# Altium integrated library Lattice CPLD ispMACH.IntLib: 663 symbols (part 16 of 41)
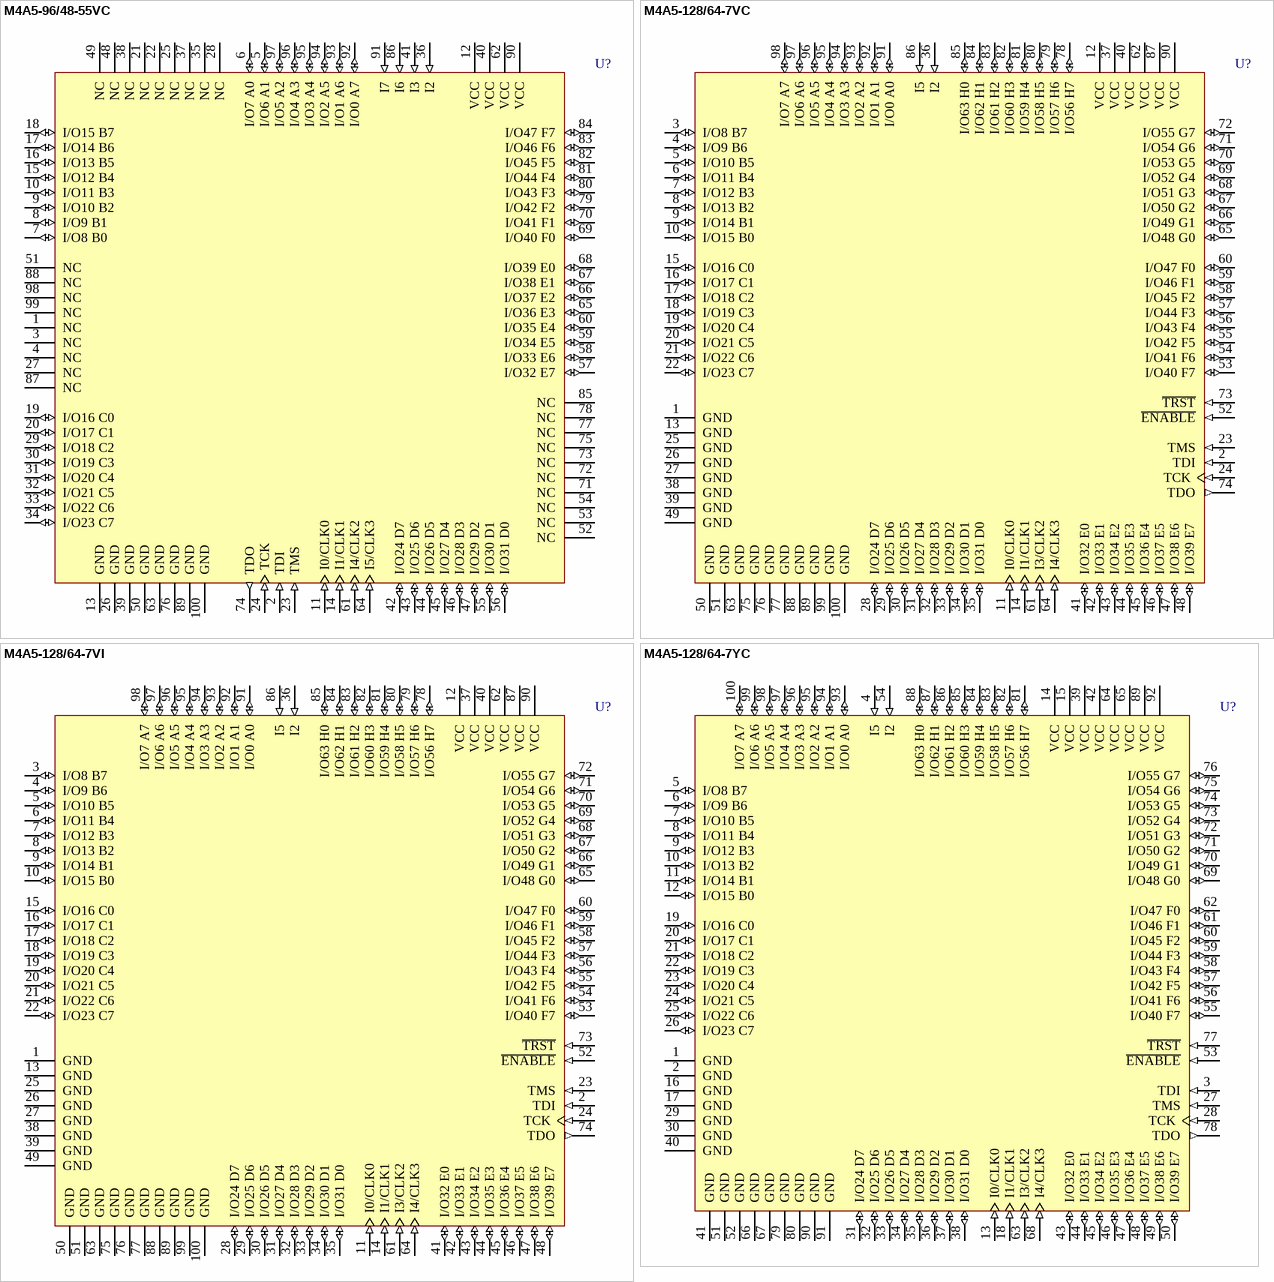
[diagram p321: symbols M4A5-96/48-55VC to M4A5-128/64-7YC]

## M4A5-128/64-7VC
designator U?
High-Performance EE CMOS In-System Programmable Logic
footprint TQFP100_N (Thin QFP, 100-Leads, Body 14x14mm, Pitch 0.5mm, IPC Medium Density)
footprint TQFP100_L (Thin QFP, 100-Leads, Body 14x14mm, Pitch 0.5mm, IPC High Density)
footprint TQFP100_M (Thin QFP, 100-Leads, Body 14x14mm, Pitch 0.5mm, IPC Low Density)
3D model M4A5-TQFP100 (100-Pin Thin Quad Flat Pack (TQFP100))
pins: 1 GND (power), 2 TDI (in), 3 I/O8 B7 (io), 4 I/O9 B6 (io), 5 I/O10 B5 (io), 6 I/O11 B4 (io), 7 I/O12 B3 (io), 8 I/O13 B2 (io), 9 I/O14 B1 (io), 10 I/O15 B0 (io), 11 I0/CLK0 (in), 12 VCC (power), 13 GND (power), 14 I1/CLK1 (in), 15 I/O16 C0 (io), 16 I/O17 C1 (io), 17 I/O18 C2 (io), 18 I/O19 C3 (io), 19 I/O20 C4 (io), 20 I/O21 C5 (io), 21 I/O22 C6 (io), 22 I/O23 C7 (io), 23 TMS (in), 24 TCK (in), 25 GND (power), 26 GND (power), 27 GND (power), 28 I/O24 D7 (io), 29 I/O25 D6 (io), 30 I/O26 D5 (io), 31 I/O27 D4 (io), 32 I/O28 D3 (io), 33 I/O29 D2 (io), 34 I/O30 D1 (io), 35 I/O31 D0 (io), 36 I2 (in), 37 VCC (power), 38 GND (power), 39 GND (power), 40 VCC (power), 41 I/O32 E0 (io), 42 I/O33 E1 (io), 43 I/O34 E2 (io), 44 I/O35 E3 (io), 45 I/O36 E4 (io), 46 I/O37 E5 (io), 47 I/O38 E6 (io), 48 I/O39 E7 (io), 49 GND (power), 50 GND (power), 51 GND (power), 52 ~{ENABLE} (in), 53 I/O40 F7 (io), 54 I/O41 F6 (io), 55 I/O42 F5 (io), 56 I/O43 F4 (io), 57 I/O44 F3 (io), 58 I/O45 F2 (io), 59 I/O46 F1 (io), 60 I/O47 F0 (io), 61 I3/CLK2 (in), 62 VCC (power), 63 GND (power), 64 I4/CLK3 (in), 65 I/O48 G0 (io), 66 I/O49 G1 (io), 67 I/O50 G2 (io), 68 I/O51 G3 (io), 69 I/O52 G4 (io), 70 I/O53 G5 (io), 71 I/O54 G6 (io), 72 I/O55 G7 (io), 73 ~{TRST} (in), 74 TDO (out), 75 GND (power), 76 GND (power), 77 GND (power), 78 I/O56 H7 (io), 79 I/O57 H6 (io), 80 I/O58 H5 (io), 81 I/O59 H4 (io), 82 I/O60 H3 (io), 83 I/O61 H2 (io), 84 I/O62 H1 (io), 85 I/O63 H0 (io), 86 I5 (in), 87 VCC (power), 88 GND (power), 89 GND (power), 90 VCC (power), 91 I/O0 A0 (io), 92 I/O1 A1 (io), 93 I/O2 A2 (io), 94 I/O3 A3 (io), 95 I/O4 A4 (io), 96 I/O5 A5 (io), 97 I/O6 A6 (io), 98 I/O7 A7 (io), 99 GND (power), 100 GND (power)

## M4A5-128/64-7VI
designator U?
High-Performance EE CMOS In-System Programmable Logic
footprint TQFP100_N (Thin QFP, 100-Leads, Body 14x14mm, Pitch 0.5mm, IPC Medium Density)
footprint TQFP100_L (Thin QFP, 100-Leads, Body 14x14mm, Pitch 0.5mm, IPC High Density)
footprint TQFP100_M (Thin QFP, 100-Leads, Body 14x14mm, Pitch 0.5mm, IPC Low Density)
3D model M4A5-TQFP100 (100-Pin Thin Quad Flat Pack (TQFP100))
pins: 1 GND (power), 2 TDI (in), 3 I/O8 B7 (io), 4 I/O9 B6 (io), 5 I/O10 B5 (io), 6 I/O11 B4 (io), 7 I/O12 B3 (io), 8 I/O13 B2 (io), 9 I/O14 B1 (io), 10 I/O15 B0 (io), 11 I0/CLK0 (in), 12 VCC (power), 13 GND (power), 14 I1/CLK1 (in), 15 I/O16 C0 (io), 16 I/O17 C1 (io), 17 I/O18 C2 (io), 18 I/O19 C3 (io), 19 I/O20 C4 (io), 20 I/O21 C5 (io), 21 I/O22 C6 (io), 22 I/O23 C7 (io), 23 TMS (in), 24 TCK (in), 25 GND (power), 26 GND (power), 27 GND (power), 28 I/O24 D7 (io), 29 I/O25 D6 (io), 30 I/O26 D5 (io), 31 I/O27 D4 (io), 32 I/O28 D3 (io), 33 I/O29 D2 (io), 34 I/O30 D1 (io), 35 I/O31 D0 (io), 36 I2 (in), 37 VCC (power), 38 GND (power), 39 GND (power), 40 VCC (power), 41 I/O32 E0 (io), 42 I/O33 E1 (io), 43 I/O34 E2 (io), 44 I/O35 E3 (io), 45 I/O36 E4 (io), 46 I/O37 E5 (io), 47 I/O38 E6 (io), 48 I/O39 E7 (io), 49 GND (power), 50 GND (power), 51 GND (power), 52 ~{ENABLE} (in), 53 I/O40 F7 (io), 54 I/O41 F6 (io), 55 I/O42 F5 (io), 56 I/O43 F4 (io), 57 I/O44 F3 (io), 58 I/O45 F2 (io), 59 I/O46 F1 (io), 60 I/O47 F0 (io), 61 I3/CLK2 (in), 62 VCC (power), 63 GND (power), 64 I4/CLK3 (in), 65 I/O48 G0 (io), 66 I/O49 G1 (io), 67 I/O50 G2 (io), 68 I/O51 G3 (io), 69 I/O52 G4 (io), 70 I/O53 G5 (io), 71 I/O54 G6 (io), 72 I/O55 G7 (io), 73 ~{TRST} (in), 74 TDO (out), 75 GND (power), 76 GND (power), 77 GND (power), 78 I/O56 H7 (io), 79 I/O57 H6 (io), 80 I/O58 H5 (io), 81 I/O59 H4 (io), 82 I/O60 H3 (io), 83 I/O61 H2 (io), 84 I/O62 H1 (io), 85 I/O63 H0 (io), 86 I5 (in), 87 VCC (power), 88 GND (power), 89 GND (power), 90 VCC (power), 91 I/O0 A0 (io), 92 I/O1 A1 (io), 93 I/O2 A2 (io), 94 I/O3 A3 (io), 95 I/O4 A4 (io), 96 I/O5 A5 (io), 97 I/O6 A6 (io), 98 I/O7 A7 (io), 99 GND (power), 100 GND (power)

## M4A5-128/64-7YC
designator U?
High-Performance EE CMOS In-System Programmable Logic
footprint PQFP100_N (QFP, 100-Leads, Body 20x14mm, Pitch 0.65mm, IPC Medium Density)
footprint PQFP100_L (QFP, 100-Leads, Body 20x14mm, Pitch 0.65mm, IPC High Density)
footprint PQFP100_M (QFP, 100-Leads, Body 20x14mm, Pitch 0.65mm, IPC Low Density)
3D model PQFP-100 (100-Pin Quad Flat Pack Rectangular 0.65 mm Pitch)
pins: 1 GND (power), 2 GND (power), 3 TDI (in), 4 I5 (in), 5 I/O8 B7 (io), 6 I/O9 B6 (io), 7 I/O10 B5 (io), 8 I/O11 B4 (io), 9 I/O12 B3 (io), 10 I/O13 B2 (io), 11 I/O14 B1 (io), 12 I/O15 B0 (io), 13 I0/CLK0 (in), 14 VCC (power), 15 VCC (power), 16 GND (power), 17 GND (power), 18 I1/CLK1 (in), 19 I/O16 C0 (io), 20 I/O17 C1 (io), 21 I/O18 C2 (io), 22 I/O19 C3 (io), 23 I/O20 C4 (io), 24 I/O21 C5 (io), 25 I/O22 C6 (io), 26 I/O23 C7 (io), 27 TMS (in), 28 TCK (in), 29 GND (power), 30 GND (power), 31 I/O24 D7 (io), 32 I/O25 D6 (io), 33 I/O26 D5 (io), 34 I/O27 D4 (io), 35 I/O28 D3 (io), 36 I/O29 D2 (io), 37 I/O30 D1 (io), 38 I/O31 D0 (io), 39 VCC (power), 40 GND (power), 41 GND (power), 42 VCC (power), 43 I/O32 E0 (io), 44 I/O33 E1 (io), 45 I/O34 E2 (io), 46 I/O35 E3 (io), 47 I/O36 E4 (io), 48 I/O37 E5 (io), 49 I/O38 E6 (io), 50 I/O39 E7 (io), 51 GND (power), 52 GND (power), 53 ~{ENABLE} (in), 54 I2 (in), 55 I/O40 F7 (io), 56 I/O41 F6 (io), 57 I/O42 F5 (io), 58 I/O43 F4 (io), 59 I/O44 F3 (io), 60 I/O45 F2 (io), 61 I/O46 F1 (io), 62 I/O47 F0 (io), 63 I3/CLK2 (in), 64 VCC (power), 65 VCC (power), 66 GND (power), 67 GND (power), 68 I4/CLK3 (in), 69 I/O48 G0 (io), 70 I/O49 G1 (io), 71 I/O50 G2 (io), 72 I/O51 G3 (io), 73 I/O52 G4 (io), 74 I/O53 G5 (io), 75 I/O54 G6 (io), 76 I/O55 G7 (io), 77 ~{TRST} (in), 78 TDO (out), 79 GND (power), 80 GND (power), 81 I/O56 H7 (io), 82 I/O57 H6 (io), 83 I/O58 H5 (io), 84 I/O59 H4 (io), 85 I/O60 H3 (io), 86 I/O61 H2 (io), 87 I/O62 H1 (io), 88 I/O63 H0 (io), 89 VCC (power), 90 GND (power), 91 GND (power), 92 VCC (power), 93 I/O0 A0 (io), 94 I/O1 A1 (io), 95 I/O2 A2 (io), 96 I/O3 A3 (io), 97 I/O4 A4 (io), 98 I/O5 A5 (io), 99 I/O6 A6 (io), 100 I/O7 A7 (io)

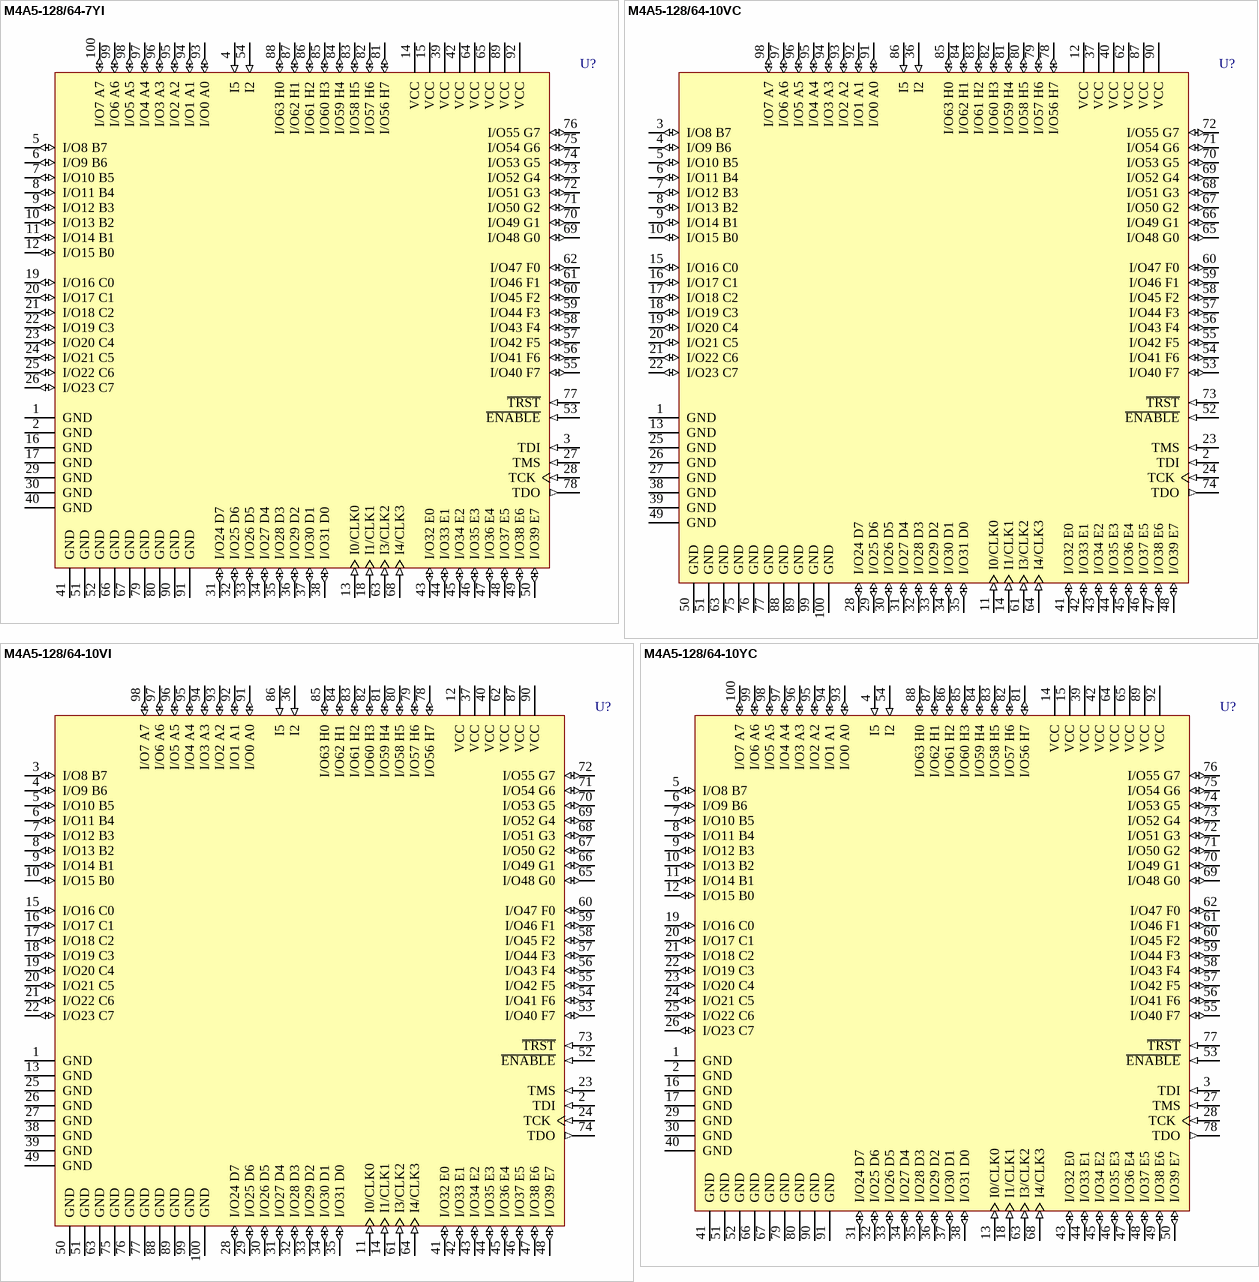
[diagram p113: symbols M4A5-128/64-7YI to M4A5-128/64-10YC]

## M4A5-128/64-7YI
designator U?
High-Performance EE CMOS In-System Programmable Logic
footprint PQFP100_N (QFP, 100-Leads, Body 20x14mm, Pitch 0.65mm, IPC Medium Density)
footprint PQFP100_L (QFP, 100-Leads, Body 20x14mm, Pitch 0.65mm, IPC High Density)
footprint PQFP100_M (QFP, 100-Leads, Body 20x14mm, Pitch 0.65mm, IPC Low Density)
3D model PQFP-100 (100-Pin Quad Flat Pack Rectangular 0.65 mm Pitch)
pins: 1 GND (power), 2 GND (power), 3 TDI (in), 4 I5 (in), 5 I/O8 B7 (io), 6 I/O9 B6 (io), 7 I/O10 B5 (io), 8 I/O11 B4 (io), 9 I/O12 B3 (io), 10 I/O13 B2 (io), 11 I/O14 B1 (io), 12 I/O15 B0 (io), 13 I0/CLK0 (in), 14 VCC (power), 15 VCC (power), 16 GND (power), 17 GND (power), 18 I1/CLK1 (in), 19 I/O16 C0 (io), 20 I/O17 C1 (io), 21 I/O18 C2 (io), 22 I/O19 C3 (io), 23 I/O20 C4 (io), 24 I/O21 C5 (io), 25 I/O22 C6 (io), 26 I/O23 C7 (io), 27 TMS (in), 28 TCK (in), 29 GND (power), 30 GND (power), 31 I/O24 D7 (io), 32 I/O25 D6 (io), 33 I/O26 D5 (io), 34 I/O27 D4 (io), 35 I/O28 D3 (io), 36 I/O29 D2 (io), 37 I/O30 D1 (io), 38 I/O31 D0 (io), 39 VCC (power), 40 GND (power), 41 GND (power), 42 VCC (power), 43 I/O32 E0 (io), 44 I/O33 E1 (io), 45 I/O34 E2 (io), 46 I/O35 E3 (io), 47 I/O36 E4 (io), 48 I/O37 E5 (io), 49 I/O38 E6 (io), 50 I/O39 E7 (io), 51 GND (power), 52 GND (power), 53 ~{ENABLE} (in), 54 I2 (in), 55 I/O40 F7 (io), 56 I/O41 F6 (io), 57 I/O42 F5 (io), 58 I/O43 F4 (io), 59 I/O44 F3 (io), 60 I/O45 F2 (io), 61 I/O46 F1 (io), 62 I/O47 F0 (io), 63 I3/CLK2 (in), 64 VCC (power), 65 VCC (power), 66 GND (power), 67 GND (power), 68 I4/CLK3 (in), 69 I/O48 G0 (io), 70 I/O49 G1 (io), 71 I/O50 G2 (io), 72 I/O51 G3 (io), 73 I/O52 G4 (io), 74 I/O53 G5 (io), 75 I/O54 G6 (io), 76 I/O55 G7 (io), 77 ~{TRST} (in), 78 TDO (out), 79 GND (power), 80 GND (power), 81 I/O56 H7 (io), 82 I/O57 H6 (io), 83 I/O58 H5 (io), 84 I/O59 H4 (io), 85 I/O60 H3 (io), 86 I/O61 H2 (io), 87 I/O62 H1 (io), 88 I/O63 H0 (io), 89 VCC (power), 90 GND (power), 91 GND (power), 92 VCC (power), 93 I/O0 A0 (io), 94 I/O1 A1 (io), 95 I/O2 A2 (io), 96 I/O3 A3 (io), 97 I/O4 A4 (io), 98 I/O5 A5 (io), 99 I/O6 A6 (io), 100 I/O7 A7 (io)

## M4A5-128/64-10VC
designator U?
High-Performance EE CMOS In-System Programmable Logic
footprint TQFP100_N (Thin QFP, 100-Leads, Body 14x14mm, Pitch 0.5mm, IPC Medium Density)
footprint TQFP100_L (Thin QFP, 100-Leads, Body 14x14mm, Pitch 0.5mm, IPC High Density)
footprint TQFP100_M (Thin QFP, 100-Leads, Body 14x14mm, Pitch 0.5mm, IPC Low Density)
3D model M4A5-TQFP100 (100-Pin Thin Quad Flat Pack (TQFP100))
pins: 1 GND (power), 2 TDI (in), 3 I/O8 B7 (io), 4 I/O9 B6 (io), 5 I/O10 B5 (io), 6 I/O11 B4 (io), 7 I/O12 B3 (io), 8 I/O13 B2 (io), 9 I/O14 B1 (io), 10 I/O15 B0 (io), 11 I0/CLK0 (in), 12 VCC (power), 13 GND (power), 14 I1/CLK1 (in), 15 I/O16 C0 (io), 16 I/O17 C1 (io), 17 I/O18 C2 (io), 18 I/O19 C3 (io), 19 I/O20 C4 (io), 20 I/O21 C5 (io), 21 I/O22 C6 (io), 22 I/O23 C7 (io), 23 TMS (in), 24 TCK (in), 25 GND (power), 26 GND (power), 27 GND (power), 28 I/O24 D7 (io), 29 I/O25 D6 (io), 30 I/O26 D5 (io), 31 I/O27 D4 (io), 32 I/O28 D3 (io), 33 I/O29 D2 (io), 34 I/O30 D1 (io), 35 I/O31 D0 (io), 36 I2 (in), 37 VCC (power), 38 GND (power), 39 GND (power), 40 VCC (power), 41 I/O32 E0 (io), 42 I/O33 E1 (io), 43 I/O34 E2 (io), 44 I/O35 E3 (io), 45 I/O36 E4 (io), 46 I/O37 E5 (io), 47 I/O38 E6 (io), 48 I/O39 E7 (io), 49 GND (power), 50 GND (power), 51 GND (power), 52 ~{ENABLE} (in), 53 I/O40 F7 (io), 54 I/O41 F6 (io), 55 I/O42 F5 (io), 56 I/O43 F4 (io), 57 I/O44 F3 (io), 58 I/O45 F2 (io), 59 I/O46 F1 (io), 60 I/O47 F0 (io), 61 I3/CLK2 (in), 62 VCC (power), 63 GND (power), 64 I4/CLK3 (in), 65 I/O48 G0 (io), 66 I/O49 G1 (io), 67 I/O50 G2 (io), 68 I/O51 G3 (io), 69 I/O52 G4 (io), 70 I/O53 G5 (io), 71 I/O54 G6 (io), 72 I/O55 G7 (io), 73 ~{TRST} (in), 74 TDO (out), 75 GND (power), 76 GND (power), 77 GND (power), 78 I/O56 H7 (io), 79 I/O57 H6 (io), 80 I/O58 H5 (io), 81 I/O59 H4 (io), 82 I/O60 H3 (io), 83 I/O61 H2 (io), 84 I/O62 H1 (io), 85 I/O63 H0 (io), 86 I5 (in), 87 VCC (power), 88 GND (power), 89 GND (power), 90 VCC (power), 91 I/O0 A0 (io), 92 I/O1 A1 (io), 93 I/O2 A2 (io), 94 I/O3 A3 (io), 95 I/O4 A4 (io), 96 I/O5 A5 (io), 97 I/O6 A6 (io), 98 I/O7 A7 (io), 99 GND (power), 100 GND (power)

## M4A5-128/64-10VI
designator U?
High-Performance EE CMOS In-System Programmable Logic
footprint TQFP100_N (Thin QFP, 100-Leads, Body 14x14mm, Pitch 0.5mm, IPC Medium Density)
footprint TQFP100_L (Thin QFP, 100-Leads, Body 14x14mm, Pitch 0.5mm, IPC High Density)
footprint TQFP100_M (Thin QFP, 100-Leads, Body 14x14mm, Pitch 0.5mm, IPC Low Density)
3D model M4A5-TQFP100 (100-Pin Thin Quad Flat Pack (TQFP100))
pins: 1 GND (power), 2 TDI (in), 3 I/O8 B7 (io), 4 I/O9 B6 (io), 5 I/O10 B5 (io), 6 I/O11 B4 (io), 7 I/O12 B3 (io), 8 I/O13 B2 (io), 9 I/O14 B1 (io), 10 I/O15 B0 (io), 11 I0/CLK0 (in), 12 VCC (power), 13 GND (power), 14 I1/CLK1 (in), 15 I/O16 C0 (io), 16 I/O17 C1 (io), 17 I/O18 C2 (io), 18 I/O19 C3 (io), 19 I/O20 C4 (io), 20 I/O21 C5 (io), 21 I/O22 C6 (io), 22 I/O23 C7 (io), 23 TMS (in), 24 TCK (in), 25 GND (power), 26 GND (power), 27 GND (power), 28 I/O24 D7 (io), 29 I/O25 D6 (io), 30 I/O26 D5 (io), 31 I/O27 D4 (io), 32 I/O28 D3 (io), 33 I/O29 D2 (io), 34 I/O30 D1 (io), 35 I/O31 D0 (io), 36 I2 (in), 37 VCC (power), 38 GND (power), 39 GND (power), 40 VCC (power), 41 I/O32 E0 (io), 42 I/O33 E1 (io), 43 I/O34 E2 (io), 44 I/O35 E3 (io), 45 I/O36 E4 (io), 46 I/O37 E5 (io), 47 I/O38 E6 (io), 48 I/O39 E7 (io), 49 GND (power), 50 GND (power), 51 GND (power), 52 ~{ENABLE} (in), 53 I/O40 F7 (io), 54 I/O41 F6 (io), 55 I/O42 F5 (io), 56 I/O43 F4 (io), 57 I/O44 F3 (io), 58 I/O45 F2 (io), 59 I/O46 F1 (io), 60 I/O47 F0 (io), 61 I3/CLK2 (in), 62 VCC (power), 63 GND (power), 64 I4/CLK3 (in), 65 I/O48 G0 (io), 66 I/O49 G1 (io), 67 I/O50 G2 (io), 68 I/O51 G3 (io), 69 I/O52 G4 (io), 70 I/O53 G5 (io), 71 I/O54 G6 (io), 72 I/O55 G7 (io), 73 ~{TRST} (in), 74 TDO (out), 75 GND (power), 76 GND (power), 77 GND (power), 78 I/O56 H7 (io), 79 I/O57 H6 (io), 80 I/O58 H5 (io), 81 I/O59 H4 (io), 82 I/O60 H3 (io), 83 I/O61 H2 (io), 84 I/O62 H1 (io), 85 I/O63 H0 (io), 86 I5 (in), 87 VCC (power), 88 GND (power), 89 GND (power), 90 VCC (power), 91 I/O0 A0 (io), 92 I/O1 A1 (io), 93 I/O2 A2 (io), 94 I/O3 A3 (io), 95 I/O4 A4 (io), 96 I/O5 A5 (io), 97 I/O6 A6 (io), 98 I/O7 A7 (io), 99 GND (power), 100 GND (power)

## M4A5-128/64-10YC
designator U?
High-Performance EE CMOS In-System Programmable Logic
footprint PQFP100_N (QFP, 100-Leads, Body 20x14mm, Pitch 0.65mm, IPC Medium Density)
footprint PQFP100_L (QFP, 100-Leads, Body 20x14mm, Pitch 0.65mm, IPC High Density)
footprint PQFP100_M (QFP, 100-Leads, Body 20x14mm, Pitch 0.65mm, IPC Low Density)
3D model PQFP-100 (100-Pin Quad Flat Pack Rectangular 0.65 mm Pitch)
pins: 1 GND (power), 2 GND (power), 3 TDI (in), 4 I5 (in), 5 I/O8 B7 (io), 6 I/O9 B6 (io), 7 I/O10 B5 (io), 8 I/O11 B4 (io), 9 I/O12 B3 (io), 10 I/O13 B2 (io), 11 I/O14 B1 (io), 12 I/O15 B0 (io), 13 I0/CLK0 (in), 14 VCC (power), 15 VCC (power), 16 GND (power), 17 GND (power), 18 I1/CLK1 (in), 19 I/O16 C0 (io), 20 I/O17 C1 (io), 21 I/O18 C2 (io), 22 I/O19 C3 (io), 23 I/O20 C4 (io), 24 I/O21 C5 (io), 25 I/O22 C6 (io), 26 I/O23 C7 (io), 27 TMS (in), 28 TCK (in), 29 GND (power), 30 GND (power), 31 I/O24 D7 (io), 32 I/O25 D6 (io), 33 I/O26 D5 (io), 34 I/O27 D4 (io), 35 I/O28 D3 (io), 36 I/O29 D2 (io), 37 I/O30 D1 (io), 38 I/O31 D0 (io), 39 VCC (power), 40 GND (power), 41 GND (power), 42 VCC (power), 43 I/O32 E0 (io), 44 I/O33 E1 (io), 45 I/O34 E2 (io), 46 I/O35 E3 (io), 47 I/O36 E4 (io), 48 I/O37 E5 (io), 49 I/O38 E6 (io), 50 I/O39 E7 (io), 51 GND (power), 52 GND (power), 53 ~{ENABLE} (in), 54 I2 (in), 55 I/O40 F7 (io), 56 I/O41 F6 (io), 57 I/O42 F5 (io), 58 I/O43 F4 (io), 59 I/O44 F3 (io), 60 I/O45 F2 (io), 61 I/O46 F1 (io), 62 I/O47 F0 (io), 63 I3/CLK2 (in), 64 VCC (power), 65 VCC (power), 66 GND (power), 67 GND (power), 68 I4/CLK3 (in), 69 I/O48 G0 (io), 70 I/O49 G1 (io), 71 I/O50 G2 (io), 72 I/O51 G3 (io), 73 I/O52 G4 (io), 74 I/O53 G5 (io), 75 I/O54 G6 (io), 76 I/O55 G7 (io), 77 ~{TRST} (in), 78 TDO (out), 79 GND (power), 80 GND (power), 81 I/O56 H7 (io), 82 I/O57 H6 (io), 83 I/O58 H5 (io), 84 I/O59 H4 (io), 85 I/O60 H3 (io), 86 I/O61 H2 (io), 87 I/O62 H1 (io), 88 I/O63 H0 (io), 89 VCC (power), 90 GND (power), 91 GND (power), 92 VCC (power), 93 I/O0 A0 (io), 94 I/O1 A1 (io), 95 I/O2 A2 (io), 96 I/O3 A3 (io), 97 I/O4 A4 (io), 98 I/O5 A5 (io), 99 I/O6 A6 (io), 100 I/O7 A7 (io)

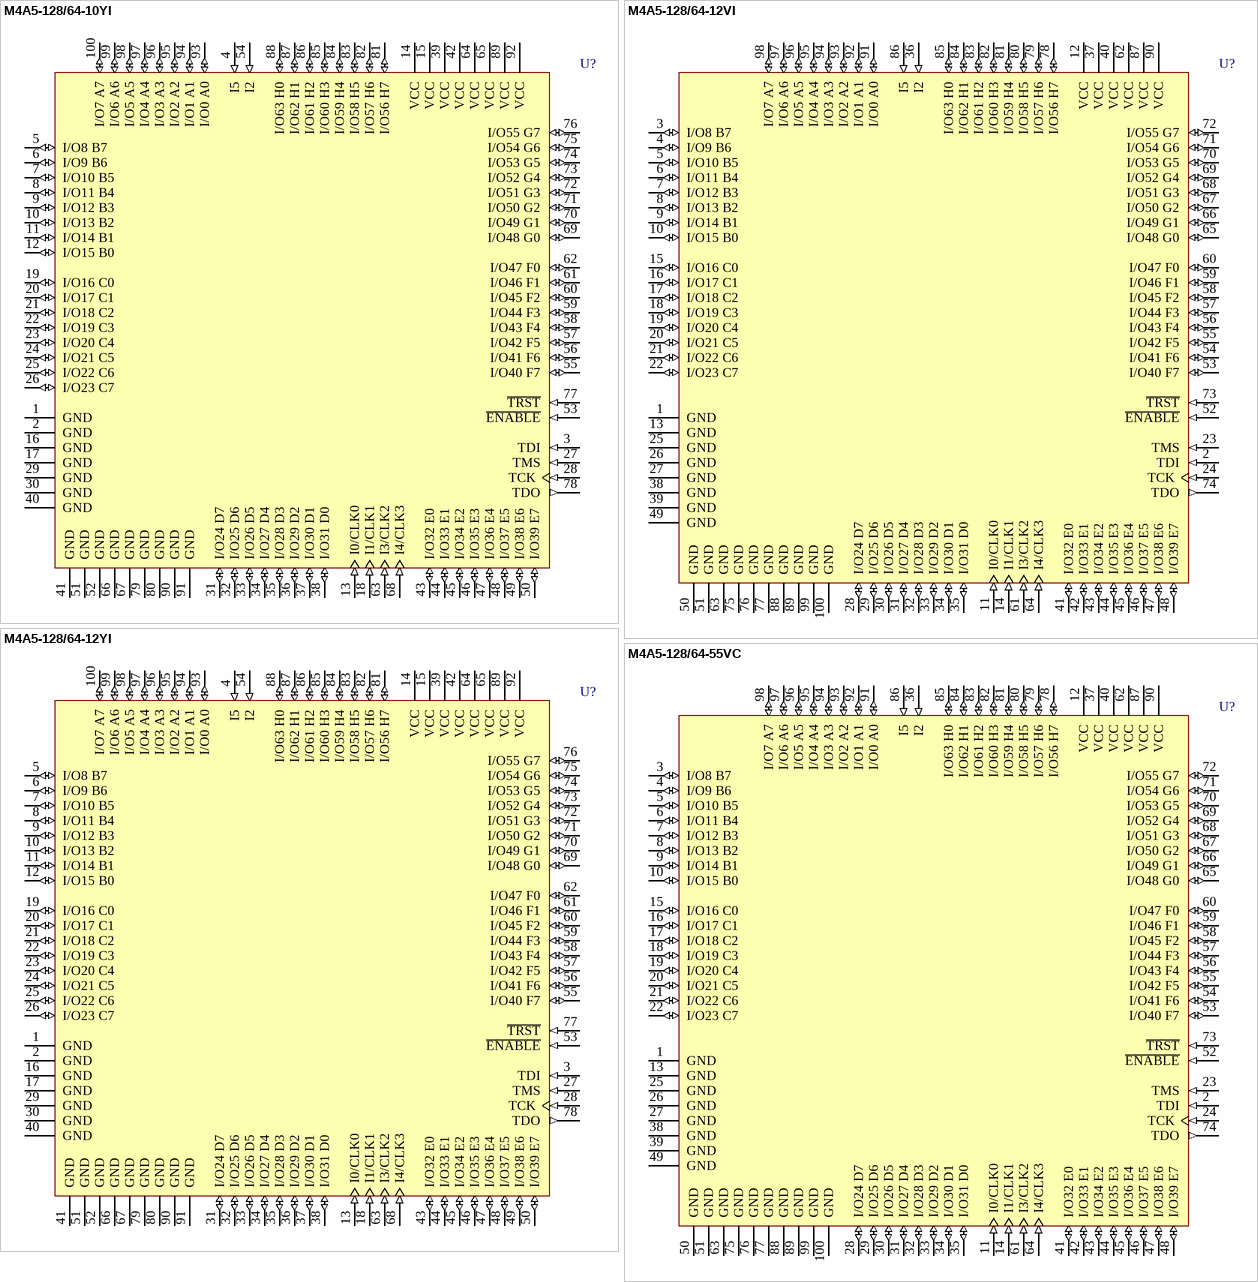
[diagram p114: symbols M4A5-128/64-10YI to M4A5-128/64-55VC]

## M4A5-128/64-10YI
designator U?
High-Performance EE CMOS In-System Programmable Logic
footprint PQFP100_N (QFP, 100-Leads, Body 20x14mm, Pitch 0.65mm, IPC Medium Density)
footprint PQFP100_L (QFP, 100-Leads, Body 20x14mm, Pitch 0.65mm, IPC High Density)
footprint PQFP100_M (QFP, 100-Leads, Body 20x14mm, Pitch 0.65mm, IPC Low Density)
3D model PQFP-100 (100-Pin Quad Flat Pack Rectangular 0.65 mm Pitch)
pins: 1 GND (power), 2 GND (power), 3 TDI (in), 4 I5 (in), 5 I/O8 B7 (io), 6 I/O9 B6 (io), 7 I/O10 B5 (io), 8 I/O11 B4 (io), 9 I/O12 B3 (io), 10 I/O13 B2 (io), 11 I/O14 B1 (io), 12 I/O15 B0 (io), 13 I0/CLK0 (in), 14 VCC (power), 15 VCC (power), 16 GND (power), 17 GND (power), 18 I1/CLK1 (in), 19 I/O16 C0 (io), 20 I/O17 C1 (io), 21 I/O18 C2 (io), 22 I/O19 C3 (io), 23 I/O20 C4 (io), 24 I/O21 C5 (io), 25 I/O22 C6 (io), 26 I/O23 C7 (io), 27 TMS (in), 28 TCK (in), 29 GND (power), 30 GND (power), 31 I/O24 D7 (io), 32 I/O25 D6 (io), 33 I/O26 D5 (io), 34 I/O27 D4 (io), 35 I/O28 D3 (io), 36 I/O29 D2 (io), 37 I/O30 D1 (io), 38 I/O31 D0 (io), 39 VCC (power), 40 GND (power), 41 GND (power), 42 VCC (power), 43 I/O32 E0 (io), 44 I/O33 E1 (io), 45 I/O34 E2 (io), 46 I/O35 E3 (io), 47 I/O36 E4 (io), 48 I/O37 E5 (io), 49 I/O38 E6 (io), 50 I/O39 E7 (io), 51 GND (power), 52 GND (power), 53 ~{ENABLE} (in), 54 I2 (in), 55 I/O40 F7 (io), 56 I/O41 F6 (io), 57 I/O42 F5 (io), 58 I/O43 F4 (io), 59 I/O44 F3 (io), 60 I/O45 F2 (io), 61 I/O46 F1 (io), 62 I/O47 F0 (io), 63 I3/CLK2 (in), 64 VCC (power), 65 VCC (power), 66 GND (power), 67 GND (power), 68 I4/CLK3 (in), 69 I/O48 G0 (io), 70 I/O49 G1 (io), 71 I/O50 G2 (io), 72 I/O51 G3 (io), 73 I/O52 G4 (io), 74 I/O53 G5 (io), 75 I/O54 G6 (io), 76 I/O55 G7 (io), 77 ~{TRST} (in), 78 TDO (out), 79 GND (power), 80 GND (power), 81 I/O56 H7 (io), 82 I/O57 H6 (io), 83 I/O58 H5 (io), 84 I/O59 H4 (io), 85 I/O60 H3 (io), 86 I/O61 H2 (io), 87 I/O62 H1 (io), 88 I/O63 H0 (io), 89 VCC (power), 90 GND (power), 91 GND (power), 92 VCC (power), 93 I/O0 A0 (io), 94 I/O1 A1 (io), 95 I/O2 A2 (io), 96 I/O3 A3 (io), 97 I/O4 A4 (io), 98 I/O5 A5 (io), 99 I/O6 A6 (io), 100 I/O7 A7 (io)

## M4A5-128/64-12VI
designator U?
High-Performance EE CMOS In-System Programmable Logic
footprint TQFP100_N (Thin QFP, 100-Leads, Body 14x14mm, Pitch 0.5mm, IPC Medium Density)
footprint TQFP100_L (Thin QFP, 100-Leads, Body 14x14mm, Pitch 0.5mm, IPC High Density)
footprint TQFP100_M (Thin QFP, 100-Leads, Body 14x14mm, Pitch 0.5mm, IPC Low Density)
3D model M4A5-TQFP100 (100-Pin Thin Quad Flat Pack (TQFP100))
pins: 1 GND (power), 2 TDI (in), 3 I/O8 B7 (io), 4 I/O9 B6 (io), 5 I/O10 B5 (io), 6 I/O11 B4 (io), 7 I/O12 B3 (io), 8 I/O13 B2 (io), 9 I/O14 B1 (io), 10 I/O15 B0 (io), 11 I0/CLK0 (in), 12 VCC (power), 13 GND (power), 14 I1/CLK1 (in), 15 I/O16 C0 (io), 16 I/O17 C1 (io), 17 I/O18 C2 (io), 18 I/O19 C3 (io), 19 I/O20 C4 (io), 20 I/O21 C5 (io), 21 I/O22 C6 (io), 22 I/O23 C7 (io), 23 TMS (in), 24 TCK (in), 25 GND (power), 26 GND (power), 27 GND (power), 28 I/O24 D7 (io), 29 I/O25 D6 (io), 30 I/O26 D5 (io), 31 I/O27 D4 (io), 32 I/O28 D3 (io), 33 I/O29 D2 (io), 34 I/O30 D1 (io), 35 I/O31 D0 (io), 36 I2 (in), 37 VCC (power), 38 GND (power), 39 GND (power), 40 VCC (power), 41 I/O32 E0 (io), 42 I/O33 E1 (io), 43 I/O34 E2 (io), 44 I/O35 E3 (io), 45 I/O36 E4 (io), 46 I/O37 E5 (io), 47 I/O38 E6 (io), 48 I/O39 E7 (io), 49 GND (power), 50 GND (power), 51 GND (power), 52 ~{ENABLE} (in), 53 I/O40 F7 (io), 54 I/O41 F6 (io), 55 I/O42 F5 (io), 56 I/O43 F4 (io), 57 I/O44 F3 (io), 58 I/O45 F2 (io), 59 I/O46 F1 (io), 60 I/O47 F0 (io), 61 I3/CLK2 (in), 62 VCC (power), 63 GND (power), 64 I4/CLK3 (in), 65 I/O48 G0 (io), 66 I/O49 G1 (io), 67 I/O50 G2 (io), 68 I/O51 G3 (io), 69 I/O52 G4 (io), 70 I/O53 G5 (io), 71 I/O54 G6 (io), 72 I/O55 G7 (io), 73 ~{TRST} (in), 74 TDO (out), 75 GND (power), 76 GND (power), 77 GND (power), 78 I/O56 H7 (io), 79 I/O57 H6 (io), 80 I/O58 H5 (io), 81 I/O59 H4 (io), 82 I/O60 H3 (io), 83 I/O61 H2 (io), 84 I/O62 H1 (io), 85 I/O63 H0 (io), 86 I5 (in), 87 VCC (power), 88 GND (power), 89 GND (power), 90 VCC (power), 91 I/O0 A0 (io), 92 I/O1 A1 (io), 93 I/O2 A2 (io), 94 I/O3 A3 (io), 95 I/O4 A4 (io), 96 I/O5 A5 (io), 97 I/O6 A6 (io), 98 I/O7 A7 (io), 99 GND (power), 100 GND (power)

## M4A5-128/64-12YI
designator U?
High-Performance EE CMOS In-System Programmable Logic
footprint PQFP100_N (QFP, 100-Leads, Body 20x14mm, Pitch 0.65mm, IPC Medium Density)
footprint PQFP100_L (QFP, 100-Leads, Body 20x14mm, Pitch 0.65mm, IPC High Density)
footprint PQFP100_M (QFP, 100-Leads, Body 20x14mm, Pitch 0.65mm, IPC Low Density)
3D model PQFP-100 (100-Pin Quad Flat Pack Rectangular 0.65 mm Pitch)
pins: 1 GND (power), 2 GND (power), 3 TDI (in), 4 I5 (in), 5 I/O8 B7 (io), 6 I/O9 B6 (io), 7 I/O10 B5 (io), 8 I/O11 B4 (io), 9 I/O12 B3 (io), 10 I/O13 B2 (io), 11 I/O14 B1 (io), 12 I/O15 B0 (io), 13 I0/CLK0 (in), 14 VCC (power), 15 VCC (power), 16 GND (power), 17 GND (power), 18 I1/CLK1 (in), 19 I/O16 C0 (io), 20 I/O17 C1 (io), 21 I/O18 C2 (io), 22 I/O19 C3 (io), 23 I/O20 C4 (io), 24 I/O21 C5 (io), 25 I/O22 C6 (io), 26 I/O23 C7 (io), 27 TMS (in), 28 TCK (in), 29 GND (power), 30 GND (power), 31 I/O24 D7 (io), 32 I/O25 D6 (io), 33 I/O26 D5 (io), 34 I/O27 D4 (io), 35 I/O28 D3 (io), 36 I/O29 D2 (io), 37 I/O30 D1 (io), 38 I/O31 D0 (io), 39 VCC (power), 40 GND (power), 41 GND (power), 42 VCC (power), 43 I/O32 E0 (io), 44 I/O33 E1 (io), 45 I/O34 E2 (io), 46 I/O35 E3 (io), 47 I/O36 E4 (io), 48 I/O37 E5 (io), 49 I/O38 E6 (io), 50 I/O39 E7 (io), 51 GND (power), 52 GND (power), 53 ~{ENABLE} (in), 54 I2 (in), 55 I/O40 F7 (io), 56 I/O41 F6 (io), 57 I/O42 F5 (io), 58 I/O43 F4 (io), 59 I/O44 F3 (io), 60 I/O45 F2 (io), 61 I/O46 F1 (io), 62 I/O47 F0 (io), 63 I3/CLK2 (in), 64 VCC (power), 65 VCC (power), 66 GND (power), 67 GND (power), 68 I4/CLK3 (in), 69 I/O48 G0 (io), 70 I/O49 G1 (io), 71 I/O50 G2 (io), 72 I/O51 G3 (io), 73 I/O52 G4 (io), 74 I/O53 G5 (io), 75 I/O54 G6 (io), 76 I/O55 G7 (io), 77 ~{TRST} (in), 78 TDO (out), 79 GND (power), 80 GND (power), 81 I/O56 H7 (io), 82 I/O57 H6 (io), 83 I/O58 H5 (io), 84 I/O59 H4 (io), 85 I/O60 H3 (io), 86 I/O61 H2 (io), 87 I/O62 H1 (io), 88 I/O63 H0 (io), 89 VCC (power), 90 GND (power), 91 GND (power), 92 VCC (power), 93 I/O0 A0 (io), 94 I/O1 A1 (io), 95 I/O2 A2 (io), 96 I/O3 A3 (io), 97 I/O4 A4 (io), 98 I/O5 A5 (io), 99 I/O6 A6 (io), 100 I/O7 A7 (io)

## M4A5-128/64-55VC
designator U?
High-Performance EE CMOS In-System Programmable Logic
footprint TQFP100_N (Thin QFP, 100-Leads, Body 14x14mm, Pitch 0.5mm, IPC Medium Density)
footprint TQFP100_L (Thin QFP, 100-Leads, Body 14x14mm, Pitch 0.5mm, IPC High Density)
footprint TQFP100_M (Thin QFP, 100-Leads, Body 14x14mm, Pitch 0.5mm, IPC Low Density)
3D model M4A5-TQFP100 (100-Pin Thin Quad Flat Pack (TQFP100))
pins: 1 GND (power), 2 TDI (in), 3 I/O8 B7 (io), 4 I/O9 B6 (io), 5 I/O10 B5 (io), 6 I/O11 B4 (io), 7 I/O12 B3 (io), 8 I/O13 B2 (io), 9 I/O14 B1 (io), 10 I/O15 B0 (io), 11 I0/CLK0 (in), 12 VCC (power), 13 GND (power), 14 I1/CLK1 (in), 15 I/O16 C0 (io), 16 I/O17 C1 (io), 17 I/O18 C2 (io), 18 I/O19 C3 (io), 19 I/O20 C4 (io), 20 I/O21 C5 (io), 21 I/O22 C6 (io), 22 I/O23 C7 (io), 23 TMS (in), 24 TCK (in), 25 GND (power), 26 GND (power), 27 GND (power), 28 I/O24 D7 (io), 29 I/O25 D6 (io), 30 I/O26 D5 (io), 31 I/O27 D4 (io), 32 I/O28 D3 (io), 33 I/O29 D2 (io), 34 I/O30 D1 (io), 35 I/O31 D0 (io), 36 I2 (in), 37 VCC (power), 38 GND (power), 39 GND (power), 40 VCC (power), 41 I/O32 E0 (io), 42 I/O33 E1 (io), 43 I/O34 E2 (io), 44 I/O35 E3 (io), 45 I/O36 E4 (io), 46 I/O37 E5 (io), 47 I/O38 E6 (io), 48 I/O39 E7 (io), 49 GND (power), 50 GND (power), 51 GND (power), 52 ~{ENABLE} (in), 53 I/O40 F7 (io), 54 I/O41 F6 (io), 55 I/O42 F5 (io), 56 I/O43 F4 (io), 57 I/O44 F3 (io), 58 I/O45 F2 (io), 59 I/O46 F1 (io), 60 I/O47 F0 (io), 61 I3/CLK2 (in), 62 VCC (power), 63 GND (power), 64 I4/CLK3 (in), 65 I/O48 G0 (io), 66 I/O49 G1 (io), 67 I/O50 G2 (io), 68 I/O51 G3 (io), 69 I/O52 G4 (io), 70 I/O53 G5 (io), 71 I/O54 G6 (io), 72 I/O55 G7 (io), 73 ~{TRST} (in), 74 TDO (out), 75 GND (power), 76 GND (power), 77 GND (power), 78 I/O56 H7 (io), 79 I/O57 H6 (io), 80 I/O58 H5 (io), 81 I/O59 H4 (io), 82 I/O60 H3 (io), 83 I/O61 H2 (io), 84 I/O62 H1 (io), 85 I/O63 H0 (io), 86 I5 (in), 87 VCC (power), 88 GND (power), 89 GND (power), 90 VCC (power), 91 I/O0 A0 (io), 92 I/O1 A1 (io), 93 I/O2 A2 (io), 94 I/O3 A3 (io), 95 I/O4 A4 (io), 96 I/O5 A5 (io), 97 I/O6 A6 (io), 98 I/O7 A7 (io), 99 GND (power), 100 GND (power)

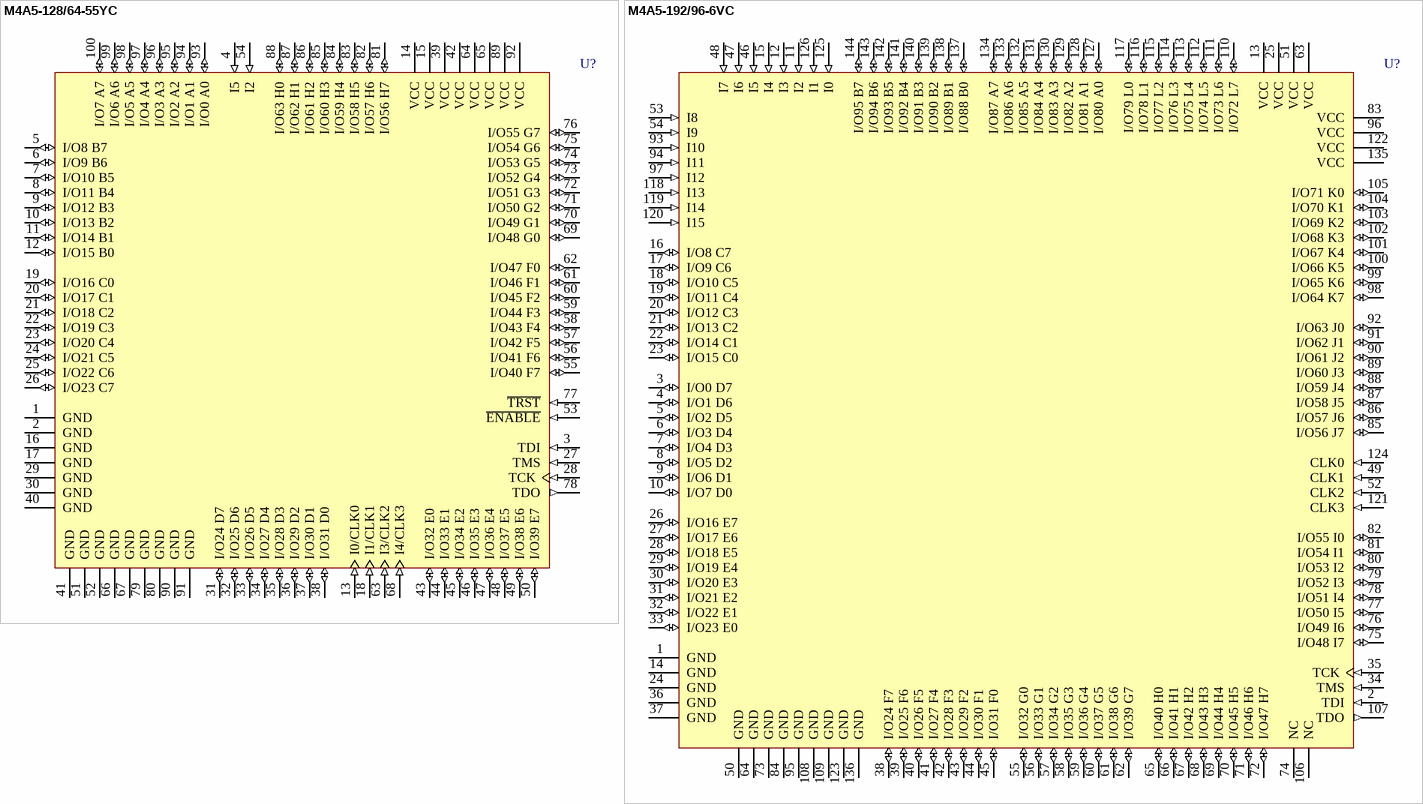
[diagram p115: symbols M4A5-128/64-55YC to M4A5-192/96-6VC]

## M4A5-128/64-55YC
designator U?
High-Performance EE CMOS In-System Programmable Logic
footprint PQFP100_N (QFP, 100-Leads, Body 20x14mm, Pitch 0.65mm, IPC Medium Density)
footprint PQFP100_L (QFP, 100-Leads, Body 20x14mm, Pitch 0.65mm, IPC High Density)
footprint PQFP100_M (QFP, 100-Leads, Body 20x14mm, Pitch 0.65mm, IPC Low Density)
3D model PQFP-100 (100-Pin Quad Flat Pack Rectangular 0.65 mm Pitch)
pins: 1 GND (power), 2 GND (power), 3 TDI (in), 4 I5 (in), 5 I/O8 B7 (io), 6 I/O9 B6 (io), 7 I/O10 B5 (io), 8 I/O11 B4 (io), 9 I/O12 B3 (io), 10 I/O13 B2 (io), 11 I/O14 B1 (io), 12 I/O15 B0 (io), 13 I0/CLK0 (in), 14 VCC (power), 15 VCC (power), 16 GND (power), 17 GND (power), 18 I1/CLK1 (in), 19 I/O16 C0 (io), 20 I/O17 C1 (io), 21 I/O18 C2 (io), 22 I/O19 C3 (io), 23 I/O20 C4 (io), 24 I/O21 C5 (io), 25 I/O22 C6 (io), 26 I/O23 C7 (io), 27 TMS (in), 28 TCK (in), 29 GND (power), 30 GND (power), 31 I/O24 D7 (io), 32 I/O25 D6 (io), 33 I/O26 D5 (io), 34 I/O27 D4 (io), 35 I/O28 D3 (io), 36 I/O29 D2 (io), 37 I/O30 D1 (io), 38 I/O31 D0 (io), 39 VCC (power), 40 GND (power), 41 GND (power), 42 VCC (power), 43 I/O32 E0 (io), 44 I/O33 E1 (io), 45 I/O34 E2 (io), 46 I/O35 E3 (io), 47 I/O36 E4 (io), 48 I/O37 E5 (io), 49 I/O38 E6 (io), 50 I/O39 E7 (io), 51 GND (power), 52 GND (power), 53 ~{ENABLE} (in), 54 I2 (in), 55 I/O40 F7 (io), 56 I/O41 F6 (io), 57 I/O42 F5 (io), 58 I/O43 F4 (io), 59 I/O44 F3 (io), 60 I/O45 F2 (io), 61 I/O46 F1 (io), 62 I/O47 F0 (io), 63 I3/CLK2 (in), 64 VCC (power), 65 VCC (power), 66 GND (power), 67 GND (power), 68 I4/CLK3 (in), 69 I/O48 G0 (io), 70 I/O49 G1 (io), 71 I/O50 G2 (io), 72 I/O51 G3 (io), 73 I/O52 G4 (io), 74 I/O53 G5 (io), 75 I/O54 G6 (io), 76 I/O55 G7 (io), 77 ~{TRST} (in), 78 TDO (out), 79 GND (power), 80 GND (power), 81 I/O56 H7 (io), 82 I/O57 H6 (io), 83 I/O58 H5 (io), 84 I/O59 H4 (io), 85 I/O60 H3 (io), 86 I/O61 H2 (io), 87 I/O62 H1 (io), 88 I/O63 H0 (io), 89 VCC (power), 90 GND (power), 91 GND (power), 92 VCC (power), 93 I/O0 A0 (io), 94 I/O1 A1 (io), 95 I/O2 A2 (io), 96 I/O3 A3 (io), 97 I/O4 A4 (io), 98 I/O5 A5 (io), 99 I/O6 A6 (io), 100 I/O7 A7 (io)

## M4A5-192/96-6VC
designator U?
High-Performance EE CMOS In-System Programmable Logic
footprint TQFP144_N (Thin QFP, 144-Leads, Body 20x20mm, Pitch 0.5mm, IPC Medium Density)
footprint TQFP144_L (Thin QFP, 144-Leads, Body 20x20mm, Pitch 0.5mm, IPC High Density)
footprint TQFP144_M (Thin QFP, 144-Leads, Body 20x20mm, Pitch 0.5mm, IPC Low Density)
3D model M4A5-TQFP144 (144-Pin Thin Quad Flat Pack (TQFP144))
pins: 1 GND (power), 2 TDI (in), 3 I/O0 D7 (io), 4 I/O1 D6 (io), 5 I/O2 D5 (io), 6 I/O3 D4 (io), 7 I/O4 D3 (io), 8 I/O5 D2 (io), 9 I/O6 D1 (io), 10 I/O7 D0 (io), 11 I2 (in), 12 I3 (in), 13 VCC (power), 14 GND (power), 15 I4 (in), 16 I/O8 C7 (io), 17 I/O9 C6 (io), 18 I/O10 C5 (io), 19 I/O11 C4 (io), 20 I/O12 C3 (io), 21 I/O13 C2 (io), 22 I/O14 C1 (io), 23 I/O15 C0 (io), 24 GND (power), 25 VCC (power), 26 I/O16 E7 (io), 27 I/O17 E6 (io), 28 I/O18 E5 (io), 29 I/O19 E4 (io), 30 I/O20 E3 (io), 31 I/O21 E2 (io), 32 I/O22 E1 (io), 33 I/O23 E0 (io), 34 TMS (in), 35 TCK (in), 36 GND (power), 37 GND (power), 38 I/O24 F7 (io), 39 I/O25 F6 (io), 40 I/O26 F5 (io), 41 I/O27 F4 (io), 42 I/O28 F3 (io), 43 I/O29 F2 (io), 44 I/O30 F1 (io), 45 I/O31 F0 (io), 46 I5 (in), 47 I6 (in), 48 I7 (in), 49 CLK1 (in), 50 GND (power), 51 VCC (power), 52 CLK2 (in), 53 I8 (in), 54 I9 (in), 55 I/O32 G0 (io), 56 I/O33 G1 (io), 57 I/O34 G2 (io), 58 I/O35 G3 (io), 59 I/O36 G4 (io), 60 I/O37 G5 (io), 61 I/O38 G6 (io), 62 I/O39 G7 (io), 63 VCC (power), 64 GND (power), 65 I/O40 H0 (io), 66 I/O41 H1 (io), 67 I/O42 H2 (io), 68 I/O43 H3 (io), 69 I/O44 H4 (io), 70 I/O45 H5 (io), 71 I/O46 H6 (io), 72 I/O47 H7 (io), 73 GND (power), 74 NC, 75 I/O48 I7 (io), 76 I/O49 I6 (io), 77 I/O50 I5 (io), 78 I/O51 I4 (io), 79 I/O52 I3 (io), 80 I/O53 I2 (io), 81 I/O54 I1 (io), 82 I/O55 I0 (io), 83 VCC (power), 84 GND (power), 85 I/O56 J7 (io), 86 I/O57 J6 (io), 87 I/O58 J5 (io), 88 I/O59 J4 (io), 89 I/O60 J3 (io), 90 I/O61 J2 (io), 91 I/O62 J1 (io), 92 I/O63 J0 (io), 93 I10 (in), 94 I11 (in), 95 GND (power), 96 VCC (power), 97 I12 (in), 98 I/O64 K7 (io), 99 I/O65 K6 (io), 100 I/O66 K5 (io), 101 I/O67 K4 (io), 102 I/O68 K3 (io), 103 I/O69 K2 (io), 104 I/O70 K1 (io), 105 I/O71 K0 (io), 106 NC, 107 TDO (out), 108 GND (power), 109 GND (power), 110 I/O72 L7 (io), 111 I/O73 L6 (io), 112 I/O74 L5 (io), 113 I/O75 L4 (io), 114 I/O76 L3 (io), 115 I/O77 L2 (io), 116 I/O78 L1 (io), 117 I/O79 L0 (io), 118 I13 (in), 119 I14 (in), 120 I15 (in), 121 CLK3 (in), 122 VCC (power), 123 GND (power), 124 CLK0 (in), 125 I0 (in), 126 I1 (in), 127 I/O80 A0 (io), 128 I/O81 A1 (io), 129 I/O82 A2 (io), 130 I/O83 A3 (io), 131 I/O84 A4 (io), 132 I/O85 A5 (io), 133 I/O86 A6 (io), 134 I/O87 A7 (io), 135 VCC (power), 136 GND (power), 137 I/O88 B0 (io), 138 I/O89 B1 (io), 139 I/O90 B2 (io), 140 I/O91 B3 (io), 141 I/O92 B4 (io), 142 I/O93 B5 (io), 143 I/O94 B6 (io), 144 I/O95 B7 (io)

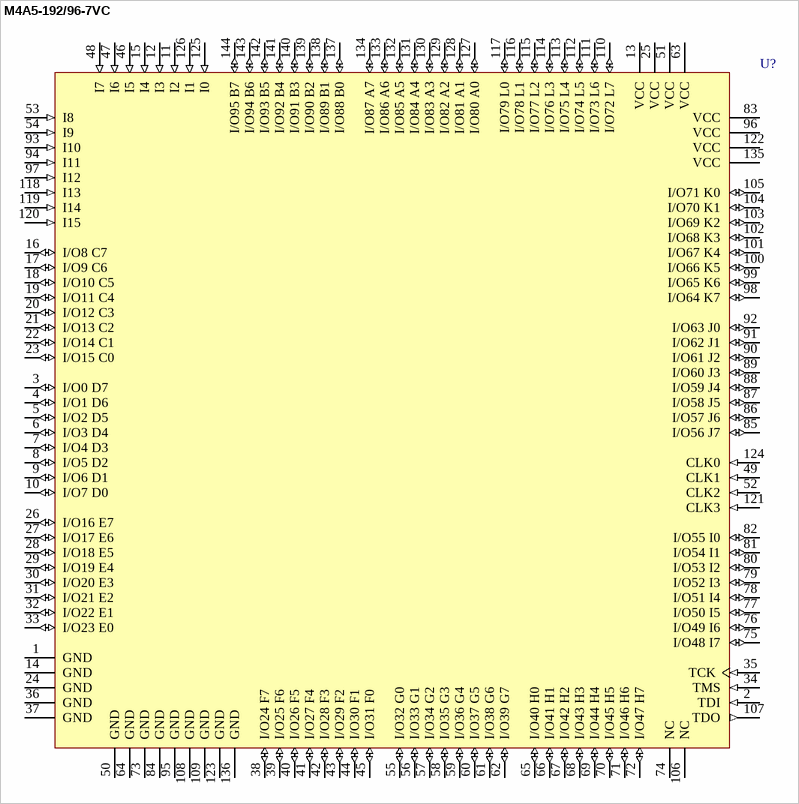
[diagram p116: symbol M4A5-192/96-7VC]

## M4A5-192/96-7VC
designator U?
High-Performance EE CMOS In-System Programmable Logic
footprint TQFP144_N (Thin QFP, 144-Leads, Body 20x20mm, Pitch 0.5mm, IPC Medium Density)
footprint TQFP144_L (Thin QFP, 144-Leads, Body 20x20mm, Pitch 0.5mm, IPC High Density)
footprint TQFP144_M (Thin QFP, 144-Leads, Body 20x20mm, Pitch 0.5mm, IPC Low Density)
3D model M4A5-TQFP144 (144-Pin Thin Quad Flat Pack (TQFP144))
pins: 1 GND (power), 2 TDI (in), 3 I/O0 D7 (io), 4 I/O1 D6 (io), 5 I/O2 D5 (io), 6 I/O3 D4 (io), 7 I/O4 D3 (io), 8 I/O5 D2 (io), 9 I/O6 D1 (io), 10 I/O7 D0 (io), 11 I2 (in), 12 I3 (in), 13 VCC (power), 14 GND (power), 15 I4 (in), 16 I/O8 C7 (io), 17 I/O9 C6 (io), 18 I/O10 C5 (io), 19 I/O11 C4 (io), 20 I/O12 C3 (io), 21 I/O13 C2 (io), 22 I/O14 C1 (io), 23 I/O15 C0 (io), 24 GND (power), 25 VCC (power), 26 I/O16 E7 (io), 27 I/O17 E6 (io), 28 I/O18 E5 (io), 29 I/O19 E4 (io), 30 I/O20 E3 (io), 31 I/O21 E2 (io), 32 I/O22 E1 (io), 33 I/O23 E0 (io), 34 TMS (in), 35 TCK (in), 36 GND (power), 37 GND (power), 38 I/O24 F7 (io), 39 I/O25 F6 (io), 40 I/O26 F5 (io), 41 I/O27 F4 (io), 42 I/O28 F3 (io), 43 I/O29 F2 (io), 44 I/O30 F1 (io), 45 I/O31 F0 (io), 46 I5 (in), 47 I6 (in), 48 I7 (in), 49 CLK1 (in), 50 GND (power), 51 VCC (power), 52 CLK2 (in), 53 I8 (in), 54 I9 (in), 55 I/O32 G0 (io), 56 I/O33 G1 (io), 57 I/O34 G2 (io), 58 I/O35 G3 (io), 59 I/O36 G4 (io), 60 I/O37 G5 (io), 61 I/O38 G6 (io), 62 I/O39 G7 (io), 63 VCC (power), 64 GND (power), 65 I/O40 H0 (io), 66 I/O41 H1 (io), 67 I/O42 H2 (io), 68 I/O43 H3 (io), 69 I/O44 H4 (io), 70 I/O45 H5 (io), 71 I/O46 H6 (io), 72 I/O47 H7 (io), 73 GND (power), 74 NC, 75 I/O48 I7 (io), 76 I/O49 I6 (io), 77 I/O50 I5 (io), 78 I/O51 I4 (io), 79 I/O52 I3 (io), 80 I/O53 I2 (io), 81 I/O54 I1 (io), 82 I/O55 I0 (io), 83 VCC (power), 84 GND (power), 85 I/O56 J7 (io), 86 I/O57 J6 (io), 87 I/O58 J5 (io), 88 I/O59 J4 (io), 89 I/O60 J3 (io), 90 I/O61 J2 (io), 91 I/O62 J1 (io), 92 I/O63 J0 (io), 93 I10 (in), 94 I11 (in), 95 GND (power), 96 VCC (power), 97 I12 (in), 98 I/O64 K7 (io), 99 I/O65 K6 (io), 100 I/O66 K5 (io), 101 I/O67 K4 (io), 102 I/O68 K3 (io), 103 I/O69 K2 (io), 104 I/O70 K1 (io), 105 I/O71 K0 (io), 106 NC, 107 TDO (out), 108 GND (power), 109 GND (power), 110 I/O72 L7 (io), 111 I/O73 L6 (io), 112 I/O74 L5 (io), 113 I/O75 L4 (io), 114 I/O76 L3 (io), 115 I/O77 L2 (io), 116 I/O78 L1 (io), 117 I/O79 L0 (io), 118 I13 (in), 119 I14 (in), 120 I15 (in), 121 CLK3 (in), 122 VCC (power), 123 GND (power), 124 CLK0 (in), 125 I0 (in), 126 I1 (in), 127 I/O80 A0 (io), 128 I/O81 A1 (io), 129 I/O82 A2 (io), 130 I/O83 A3 (io), 131 I/O84 A4 (io), 132 I/O85 A5 (io), 133 I/O86 A6 (io), 134 I/O87 A7 (io), 135 VCC (power), 136 GND (power), 137 I/O88 B0 (io), 138 I/O89 B1 (io), 139 I/O90 B2 (io), 140 I/O91 B3 (io), 141 I/O92 B4 (io), 142 I/O93 B5 (io), 143 I/O94 B6 (io), 144 I/O95 B7 (io)

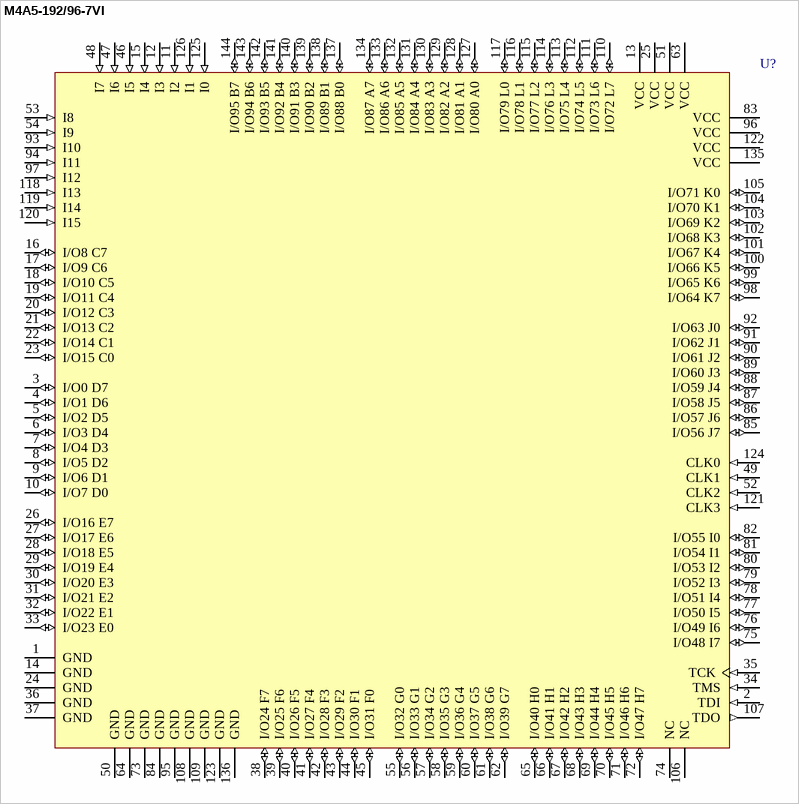
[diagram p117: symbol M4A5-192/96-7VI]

## M4A5-192/96-7VI
designator U?
High-Performance EE CMOS In-System Programmable Logic
footprint TQFP144_N (Thin QFP, 144-Leads, Body 20x20mm, Pitch 0.5mm, IPC Medium Density)
footprint TQFP144_L (Thin QFP, 144-Leads, Body 20x20mm, Pitch 0.5mm, IPC High Density)
footprint TQFP144_M (Thin QFP, 144-Leads, Body 20x20mm, Pitch 0.5mm, IPC Low Density)
3D model M4A5-TQFP144 (144-Pin Thin Quad Flat Pack (TQFP144))
pins: 1 GND (power), 2 TDI (in), 3 I/O0 D7 (io), 4 I/O1 D6 (io), 5 I/O2 D5 (io), 6 I/O3 D4 (io), 7 I/O4 D3 (io), 8 I/O5 D2 (io), 9 I/O6 D1 (io), 10 I/O7 D0 (io), 11 I2 (in), 12 I3 (in), 13 VCC (power), 14 GND (power), 15 I4 (in), 16 I/O8 C7 (io), 17 I/O9 C6 (io), 18 I/O10 C5 (io), 19 I/O11 C4 (io), 20 I/O12 C3 (io), 21 I/O13 C2 (io), 22 I/O14 C1 (io), 23 I/O15 C0 (io), 24 GND (power), 25 VCC (power), 26 I/O16 E7 (io), 27 I/O17 E6 (io), 28 I/O18 E5 (io), 29 I/O19 E4 (io), 30 I/O20 E3 (io), 31 I/O21 E2 (io), 32 I/O22 E1 (io), 33 I/O23 E0 (io), 34 TMS (in), 35 TCK (in), 36 GND (power), 37 GND (power), 38 I/O24 F7 (io), 39 I/O25 F6 (io), 40 I/O26 F5 (io), 41 I/O27 F4 (io), 42 I/O28 F3 (io), 43 I/O29 F2 (io), 44 I/O30 F1 (io), 45 I/O31 F0 (io), 46 I5 (in), 47 I6 (in), 48 I7 (in), 49 CLK1 (in), 50 GND (power), 51 VCC (power), 52 CLK2 (in), 53 I8 (in), 54 I9 (in), 55 I/O32 G0 (io), 56 I/O33 G1 (io), 57 I/O34 G2 (io), 58 I/O35 G3 (io), 59 I/O36 G4 (io), 60 I/O37 G5 (io), 61 I/O38 G6 (io), 62 I/O39 G7 (io), 63 VCC (power), 64 GND (power), 65 I/O40 H0 (io), 66 I/O41 H1 (io), 67 I/O42 H2 (io), 68 I/O43 H3 (io), 69 I/O44 H4 (io), 70 I/O45 H5 (io), 71 I/O46 H6 (io), 72 I/O47 H7 (io), 73 GND (power), 74 NC, 75 I/O48 I7 (io), 76 I/O49 I6 (io), 77 I/O50 I5 (io), 78 I/O51 I4 (io), 79 I/O52 I3 (io), 80 I/O53 I2 (io), 81 I/O54 I1 (io), 82 I/O55 I0 (io), 83 VCC (power), 84 GND (power), 85 I/O56 J7 (io), 86 I/O57 J6 (io), 87 I/O58 J5 (io), 88 I/O59 J4 (io), 89 I/O60 J3 (io), 90 I/O61 J2 (io), 91 I/O62 J1 (io), 92 I/O63 J0 (io), 93 I10 (in), 94 I11 (in), 95 GND (power), 96 VCC (power), 97 I12 (in), 98 I/O64 K7 (io), 99 I/O65 K6 (io), 100 I/O66 K5 (io), 101 I/O67 K4 (io), 102 I/O68 K3 (io), 103 I/O69 K2 (io), 104 I/O70 K1 (io), 105 I/O71 K0 (io), 106 NC, 107 TDO (out), 108 GND (power), 109 GND (power), 110 I/O72 L7 (io), 111 I/O73 L6 (io), 112 I/O74 L5 (io), 113 I/O75 L4 (io), 114 I/O76 L3 (io), 115 I/O77 L2 (io), 116 I/O78 L1 (io), 117 I/O79 L0 (io), 118 I13 (in), 119 I14 (in), 120 I15 (in), 121 CLK3 (in), 122 VCC (power), 123 GND (power), 124 CLK0 (in), 125 I0 (in), 126 I1 (in), 127 I/O80 A0 (io), 128 I/O81 A1 (io), 129 I/O82 A2 (io), 130 I/O83 A3 (io), 131 I/O84 A4 (io), 132 I/O85 A5 (io), 133 I/O86 A6 (io), 134 I/O87 A7 (io), 135 VCC (power), 136 GND (power), 137 I/O88 B0 (io), 138 I/O89 B1 (io), 139 I/O90 B2 (io), 140 I/O91 B3 (io), 141 I/O92 B4 (io), 142 I/O93 B5 (io), 143 I/O94 B6 (io), 144 I/O95 B7 (io)

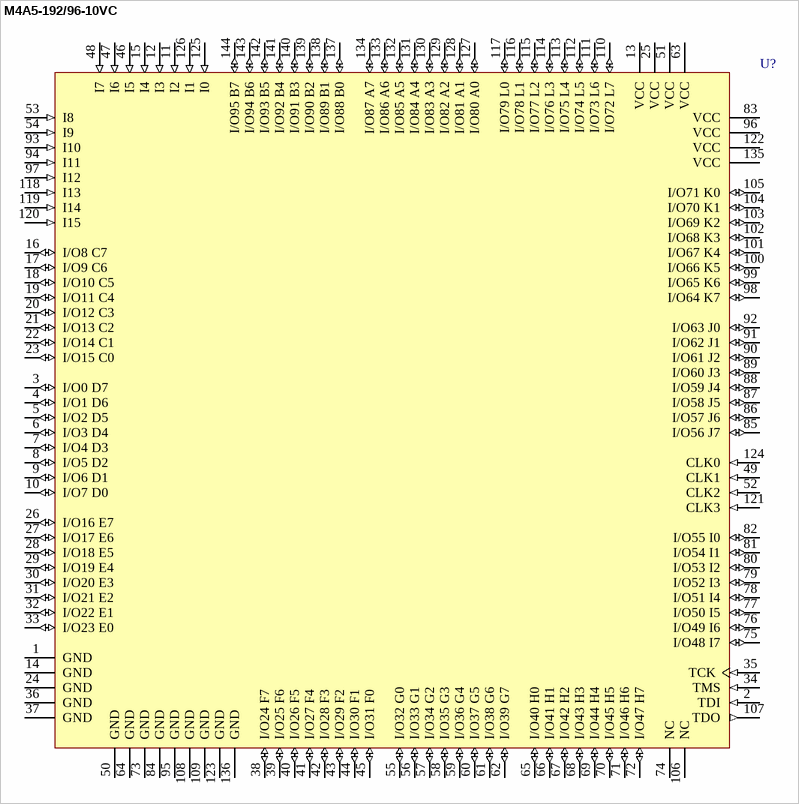
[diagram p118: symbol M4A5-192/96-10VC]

## M4A5-192/96-10VC
designator U?
High-Performance EE CMOS In-System Programmable Logic
footprint TQFP144_N (Thin QFP, 144-Leads, Body 20x20mm, Pitch 0.5mm, IPC Medium Density)
footprint TQFP144_L (Thin QFP, 144-Leads, Body 20x20mm, Pitch 0.5mm, IPC High Density)
footprint TQFP144_M (Thin QFP, 144-Leads, Body 20x20mm, Pitch 0.5mm, IPC Low Density)
3D model M4A5-TQFP144 (144-Pin Thin Quad Flat Pack (TQFP144))
pins: 1 GND (power), 2 TDI (in), 3 I/O0 D7 (io), 4 I/O1 D6 (io), 5 I/O2 D5 (io), 6 I/O3 D4 (io), 7 I/O4 D3 (io), 8 I/O5 D2 (io), 9 I/O6 D1 (io), 10 I/O7 D0 (io), 11 I2 (in), 12 I3 (in), 13 VCC (power), 14 GND (power), 15 I4 (in), 16 I/O8 C7 (io), 17 I/O9 C6 (io), 18 I/O10 C5 (io), 19 I/O11 C4 (io), 20 I/O12 C3 (io), 21 I/O13 C2 (io), 22 I/O14 C1 (io), 23 I/O15 C0 (io), 24 GND (power), 25 VCC (power), 26 I/O16 E7 (io), 27 I/O17 E6 (io), 28 I/O18 E5 (io), 29 I/O19 E4 (io), 30 I/O20 E3 (io), 31 I/O21 E2 (io), 32 I/O22 E1 (io), 33 I/O23 E0 (io), 34 TMS (in), 35 TCK (in), 36 GND (power), 37 GND (power), 38 I/O24 F7 (io), 39 I/O25 F6 (io), 40 I/O26 F5 (io), 41 I/O27 F4 (io), 42 I/O28 F3 (io), 43 I/O29 F2 (io), 44 I/O30 F1 (io), 45 I/O31 F0 (io), 46 I5 (in), 47 I6 (in), 48 I7 (in), 49 CLK1 (in), 50 GND (power), 51 VCC (power), 52 CLK2 (in), 53 I8 (in), 54 I9 (in), 55 I/O32 G0 (io), 56 I/O33 G1 (io), 57 I/O34 G2 (io), 58 I/O35 G3 (io), 59 I/O36 G4 (io), 60 I/O37 G5 (io), 61 I/O38 G6 (io), 62 I/O39 G7 (io), 63 VCC (power), 64 GND (power), 65 I/O40 H0 (io), 66 I/O41 H1 (io), 67 I/O42 H2 (io), 68 I/O43 H3 (io), 69 I/O44 H4 (io), 70 I/O45 H5 (io), 71 I/O46 H6 (io), 72 I/O47 H7 (io), 73 GND (power), 74 NC, 75 I/O48 I7 (io), 76 I/O49 I6 (io), 77 I/O50 I5 (io), 78 I/O51 I4 (io), 79 I/O52 I3 (io), 80 I/O53 I2 (io), 81 I/O54 I1 (io), 82 I/O55 I0 (io), 83 VCC (power), 84 GND (power), 85 I/O56 J7 (io), 86 I/O57 J6 (io), 87 I/O58 J5 (io), 88 I/O59 J4 (io), 89 I/O60 J3 (io), 90 I/O61 J2 (io), 91 I/O62 J1 (io), 92 I/O63 J0 (io), 93 I10 (in), 94 I11 (in), 95 GND (power), 96 VCC (power), 97 I12 (in), 98 I/O64 K7 (io), 99 I/O65 K6 (io), 100 I/O66 K5 (io), 101 I/O67 K4 (io), 102 I/O68 K3 (io), 103 I/O69 K2 (io), 104 I/O70 K1 (io), 105 I/O71 K0 (io), 106 NC, 107 TDO (out), 108 GND (power), 109 GND (power), 110 I/O72 L7 (io), 111 I/O73 L6 (io), 112 I/O74 L5 (io), 113 I/O75 L4 (io), 114 I/O76 L3 (io), 115 I/O77 L2 (io), 116 I/O78 L1 (io), 117 I/O79 L0 (io), 118 I13 (in), 119 I14 (in), 120 I15 (in), 121 CLK3 (in), 122 VCC (power), 123 GND (power), 124 CLK0 (in), 125 I0 (in), 126 I1 (in), 127 I/O80 A0 (io), 128 I/O81 A1 (io), 129 I/O82 A2 (io), 130 I/O83 A3 (io), 131 I/O84 A4 (io), 132 I/O85 A5 (io), 133 I/O86 A6 (io), 134 I/O87 A7 (io), 135 VCC (power), 136 GND (power), 137 I/O88 B0 (io), 138 I/O89 B1 (io), 139 I/O90 B2 (io), 140 I/O91 B3 (io), 141 I/O92 B4 (io), 142 I/O93 B5 (io), 143 I/O94 B6 (io), 144 I/O95 B7 (io)

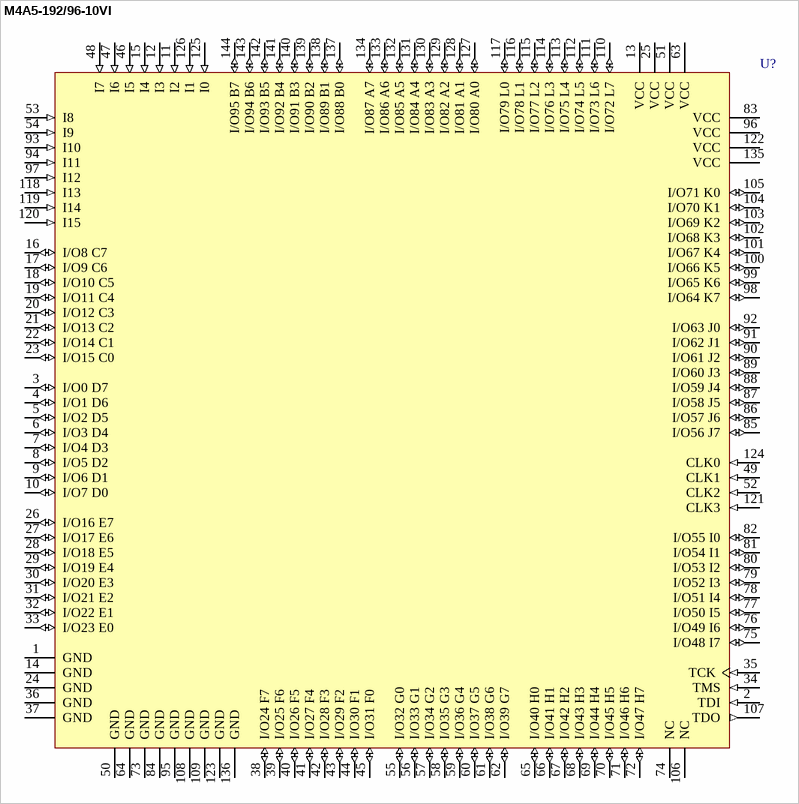
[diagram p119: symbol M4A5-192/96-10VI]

## M4A5-192/96-10VI
designator U?
High-Performance EE CMOS In-System Programmable Logic
footprint TQFP144_N (Thin QFP, 144-Leads, Body 20x20mm, Pitch 0.5mm, IPC Medium Density)
footprint TQFP144_L (Thin QFP, 144-Leads, Body 20x20mm, Pitch 0.5mm, IPC High Density)
footprint TQFP144_M (Thin QFP, 144-Leads, Body 20x20mm, Pitch 0.5mm, IPC Low Density)
3D model M4A5-TQFP144 (144-Pin Thin Quad Flat Pack (TQFP144))
pins: 1 GND (power), 2 TDI (in), 3 I/O0 D7 (io), 4 I/O1 D6 (io), 5 I/O2 D5 (io), 6 I/O3 D4 (io), 7 I/O4 D3 (io), 8 I/O5 D2 (io), 9 I/O6 D1 (io), 10 I/O7 D0 (io), 11 I2 (in), 12 I3 (in), 13 VCC (power), 14 GND (power), 15 I4 (in), 16 I/O8 C7 (io), 17 I/O9 C6 (io), 18 I/O10 C5 (io), 19 I/O11 C4 (io), 20 I/O12 C3 (io), 21 I/O13 C2 (io), 22 I/O14 C1 (io), 23 I/O15 C0 (io), 24 GND (power), 25 VCC (power), 26 I/O16 E7 (io), 27 I/O17 E6 (io), 28 I/O18 E5 (io), 29 I/O19 E4 (io), 30 I/O20 E3 (io), 31 I/O21 E2 (io), 32 I/O22 E1 (io), 33 I/O23 E0 (io), 34 TMS (in), 35 TCK (in), 36 GND (power), 37 GND (power), 38 I/O24 F7 (io), 39 I/O25 F6 (io), 40 I/O26 F5 (io), 41 I/O27 F4 (io), 42 I/O28 F3 (io), 43 I/O29 F2 (io), 44 I/O30 F1 (io), 45 I/O31 F0 (io), 46 I5 (in), 47 I6 (in), 48 I7 (in), 49 CLK1 (in), 50 GND (power), 51 VCC (power), 52 CLK2 (in), 53 I8 (in), 54 I9 (in), 55 I/O32 G0 (io), 56 I/O33 G1 (io), 57 I/O34 G2 (io), 58 I/O35 G3 (io), 59 I/O36 G4 (io), 60 I/O37 G5 (io), 61 I/O38 G6 (io), 62 I/O39 G7 (io), 63 VCC (power), 64 GND (power), 65 I/O40 H0 (io), 66 I/O41 H1 (io), 67 I/O42 H2 (io), 68 I/O43 H3 (io), 69 I/O44 H4 (io), 70 I/O45 H5 (io), 71 I/O46 H6 (io), 72 I/O47 H7 (io), 73 GND (power), 74 NC, 75 I/O48 I7 (io), 76 I/O49 I6 (io), 77 I/O50 I5 (io), 78 I/O51 I4 (io), 79 I/O52 I3 (io), 80 I/O53 I2 (io), 81 I/O54 I1 (io), 82 I/O55 I0 (io), 83 VCC (power), 84 GND (power), 85 I/O56 J7 (io), 86 I/O57 J6 (io), 87 I/O58 J5 (io), 88 I/O59 J4 (io), 89 I/O60 J3 (io), 90 I/O61 J2 (io), 91 I/O62 J1 (io), 92 I/O63 J0 (io), 93 I10 (in), 94 I11 (in), 95 GND (power), 96 VCC (power), 97 I12 (in), 98 I/O64 K7 (io), 99 I/O65 K6 (io), 100 I/O66 K5 (io), 101 I/O67 K4 (io), 102 I/O68 K3 (io), 103 I/O69 K2 (io), 104 I/O70 K1 (io), 105 I/O71 K0 (io), 106 NC, 107 TDO (out), 108 GND (power), 109 GND (power), 110 I/O72 L7 (io), 111 I/O73 L6 (io), 112 I/O74 L5 (io), 113 I/O75 L4 (io), 114 I/O76 L3 (io), 115 I/O77 L2 (io), 116 I/O78 L1 (io), 117 I/O79 L0 (io), 118 I13 (in), 119 I14 (in), 120 I15 (in), 121 CLK3 (in), 122 VCC (power), 123 GND (power), 124 CLK0 (in), 125 I0 (in), 126 I1 (in), 127 I/O80 A0 (io), 128 I/O81 A1 (io), 129 I/O82 A2 (io), 130 I/O83 A3 (io), 131 I/O84 A4 (io), 132 I/O85 A5 (io), 133 I/O86 A6 (io), 134 I/O87 A7 (io), 135 VCC (power), 136 GND (power), 137 I/O88 B0 (io), 138 I/O89 B1 (io), 139 I/O90 B2 (io), 140 I/O91 B3 (io), 141 I/O92 B4 (io), 142 I/O93 B5 (io), 143 I/O94 B6 (io), 144 I/O95 B7 (io)

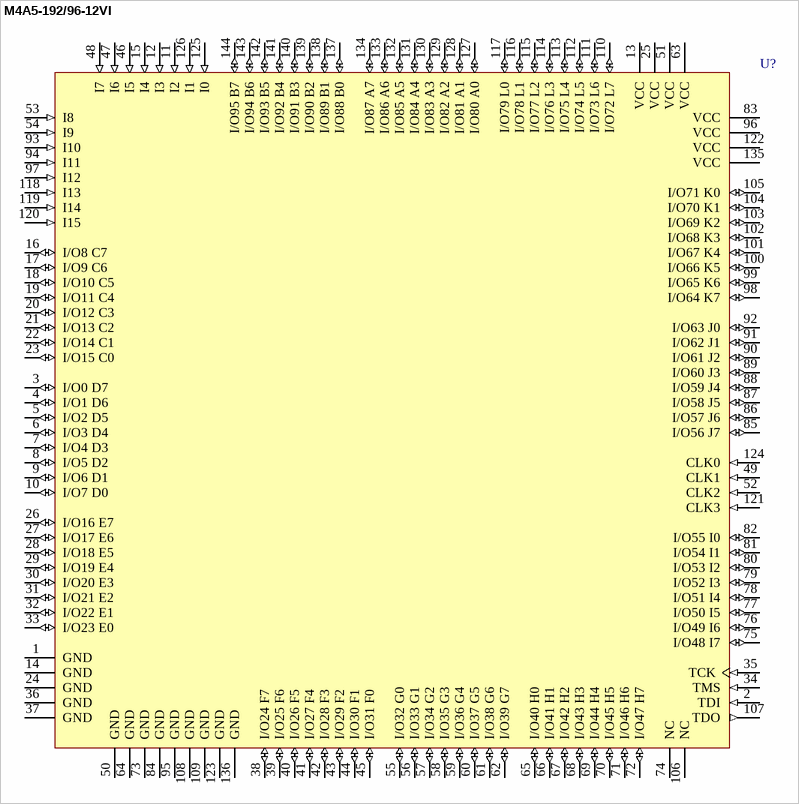
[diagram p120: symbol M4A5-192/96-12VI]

## M4A5-192/96-12VI
designator U?
High-Performance EE CMOS In-System Programmable Logic
footprint TQFP144_N (Thin QFP, 144-Leads, Body 20x20mm, Pitch 0.5mm, IPC Medium Density)
footprint TQFP144_L (Thin QFP, 144-Leads, Body 20x20mm, Pitch 0.5mm, IPC High Density)
footprint TQFP144_M (Thin QFP, 144-Leads, Body 20x20mm, Pitch 0.5mm, IPC Low Density)
3D model M4A5-TQFP144 (144-Pin Thin Quad Flat Pack (TQFP144))
pins: 1 GND (power), 2 TDI (in), 3 I/O0 D7 (io), 4 I/O1 D6 (io), 5 I/O2 D5 (io), 6 I/O3 D4 (io), 7 I/O4 D3 (io), 8 I/O5 D2 (io), 9 I/O6 D1 (io), 10 I/O7 D0 (io), 11 I2 (in), 12 I3 (in), 13 VCC (power), 14 GND (power), 15 I4 (in), 16 I/O8 C7 (io), 17 I/O9 C6 (io), 18 I/O10 C5 (io), 19 I/O11 C4 (io), 20 I/O12 C3 (io), 21 I/O13 C2 (io), 22 I/O14 C1 (io), 23 I/O15 C0 (io), 24 GND (power), 25 VCC (power), 26 I/O16 E7 (io), 27 I/O17 E6 (io), 28 I/O18 E5 (io), 29 I/O19 E4 (io), 30 I/O20 E3 (io), 31 I/O21 E2 (io), 32 I/O22 E1 (io), 33 I/O23 E0 (io), 34 TMS (in), 35 TCK (in), 36 GND (power), 37 GND (power), 38 I/O24 F7 (io), 39 I/O25 F6 (io), 40 I/O26 F5 (io), 41 I/O27 F4 (io), 42 I/O28 F3 (io), 43 I/O29 F2 (io), 44 I/O30 F1 (io), 45 I/O31 F0 (io), 46 I5 (in), 47 I6 (in), 48 I7 (in), 49 CLK1 (in), 50 GND (power), 51 VCC (power), 52 CLK2 (in), 53 I8 (in), 54 I9 (in), 55 I/O32 G0 (io), 56 I/O33 G1 (io), 57 I/O34 G2 (io), 58 I/O35 G3 (io), 59 I/O36 G4 (io), 60 I/O37 G5 (io), 61 I/O38 G6 (io), 62 I/O39 G7 (io), 63 VCC (power), 64 GND (power), 65 I/O40 H0 (io), 66 I/O41 H1 (io), 67 I/O42 H2 (io), 68 I/O43 H3 (io), 69 I/O44 H4 (io), 70 I/O45 H5 (io), 71 I/O46 H6 (io), 72 I/O47 H7 (io), 73 GND (power), 74 NC, 75 I/O48 I7 (io), 76 I/O49 I6 (io), 77 I/O50 I5 (io), 78 I/O51 I4 (io), 79 I/O52 I3 (io), 80 I/O53 I2 (io), 81 I/O54 I1 (io), 82 I/O55 I0 (io), 83 VCC (power), 84 GND (power), 85 I/O56 J7 (io), 86 I/O57 J6 (io), 87 I/O58 J5 (io), 88 I/O59 J4 (io), 89 I/O60 J3 (io), 90 I/O61 J2 (io), 91 I/O62 J1 (io), 92 I/O63 J0 (io), 93 I10 (in), 94 I11 (in), 95 GND (power), 96 VCC (power), 97 I12 (in), 98 I/O64 K7 (io), 99 I/O65 K6 (io), 100 I/O66 K5 (io), 101 I/O67 K4 (io), 102 I/O68 K3 (io), 103 I/O69 K2 (io), 104 I/O70 K1 (io), 105 I/O71 K0 (io), 106 NC, 107 TDO (out), 108 GND (power), 109 GND (power), 110 I/O72 L7 (io), 111 I/O73 L6 (io), 112 I/O74 L5 (io), 113 I/O75 L4 (io), 114 I/O76 L3 (io), 115 I/O77 L2 (io), 116 I/O78 L1 (io), 117 I/O79 L0 (io), 118 I13 (in), 119 I14 (in), 120 I15 (in), 121 CLK3 (in), 122 VCC (power), 123 GND (power), 124 CLK0 (in), 125 I0 (in), 126 I1 (in), 127 I/O80 A0 (io), 128 I/O81 A1 (io), 129 I/O82 A2 (io), 130 I/O83 A3 (io), 131 I/O84 A4 (io), 132 I/O85 A5 (io), 133 I/O86 A6 (io), 134 I/O87 A7 (io), 135 VCC (power), 136 GND (power), 137 I/O88 B0 (io), 138 I/O89 B1 (io), 139 I/O90 B2 (io), 140 I/O91 B3 (io), 141 I/O92 B4 (io), 142 I/O93 B5 (io), 143 I/O94 B6 (io), 144 I/O95 B7 (io)

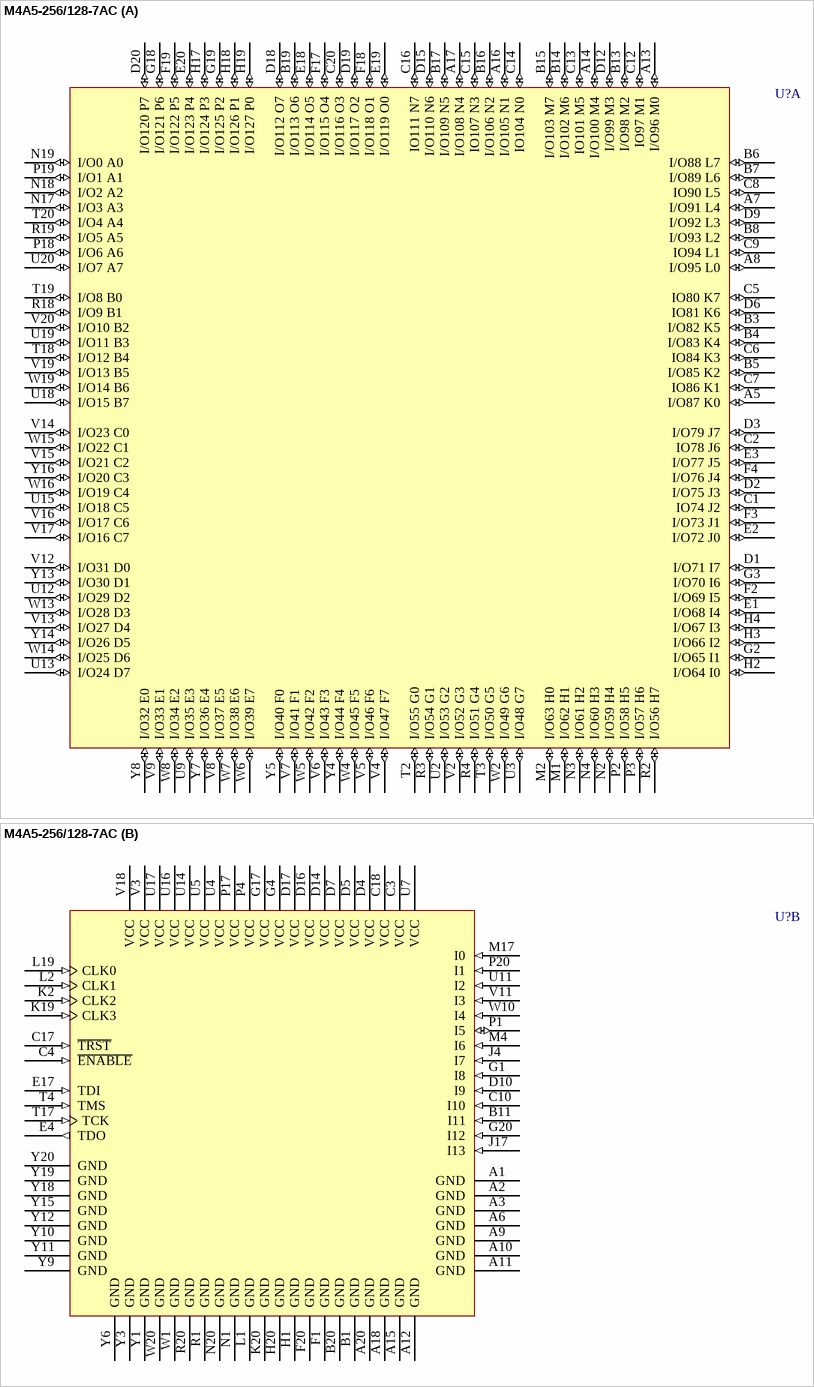
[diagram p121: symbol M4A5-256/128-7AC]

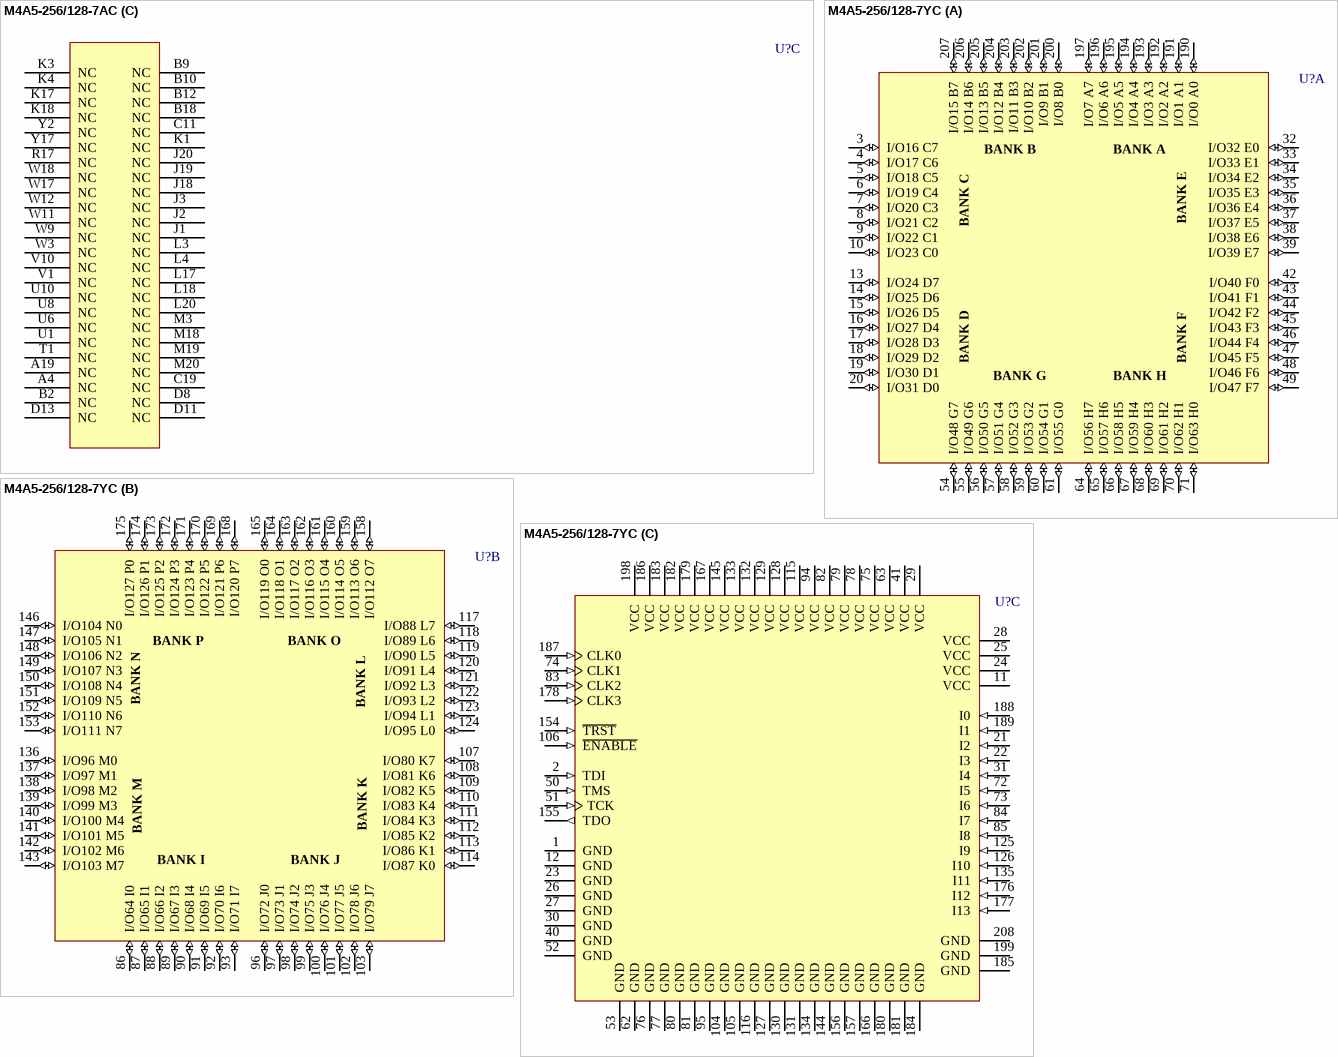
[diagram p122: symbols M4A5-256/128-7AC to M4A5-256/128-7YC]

## M4A5-256/128-7AC
designator U?
High-Performance EE CMOS In-System Programmable Logic
footprint SBGA256 (BGA, 256-Leads, Body 27x27mm, Pitch 1.27mm)
3D model M4A5-SBGA256 (256-Ball Super Ball Grid Array (SBGA256))
part A pins: A5 I/O87 K0 (io), A7 I/O91 L4 (io), A8 I/O95 L0 (io), A13 I/O96 M0 (io), A14 I/O100 M4 (io), A16 I/O105 N1 (io), A17 I/O108 N4 (io), B3 I/O82 K5 (io), B4 I/O83 K4 (io), B5 I/O85 K2 (io), B6 I/O88 L7 (io), B7 I/O89 L6 (io), B8 I/O93 L2 (io), B13 I/O98 M2 (io), B14 I/O102 M6 (io), B15 I/O103 M7 (io), B16 I/O106 N2 (io), B17 I/O109 N5 (io), B19 I/O113 O6 (io), C1 IO74 J2 (io), C2 IO78 J6 (io), C5 IO80 K7 (io), C6 IO84 K3 (io), C7 IO86 K1 (io), C8 IO90 L5 (io), C9 IO94 L1 (io), C12 IO97 M1 (io), C13 IO101 M5 (io), C14 IO104 N0 (io), C15 IO107 N3 (io), C16 IO111 N7 (io), C20 I/O116 O3 (io), D1 I/O71 I7 (io), D2 I/O75 J3 (io), D3 I/O79 J7 (io), D6 IO81 K6 (io), D9 I/O92 L3 (io), D12 I/O99 M3 (io), D15 I/O110 N6 (io), D18 I/O112 O7 (io), D19 I/O117 O2 (io), D20 I/O120 P7 (io), E1 I/O68 I4 (io), E2 I/O72 J0 (io), E3 I/O77 J5 (io), E18 I/O114 O5 (io), E19 I/O119 O0 (io), E20 I/O123 P4 (io), F2 I/O69 I5 (io), F3 I/O73 J1 (io), F4 I/O76 J4 (io), F17 I/O115 O4 (io), F18 I/O118 O1 (io), F19 I/O122 P5 (io), G2 I/O65 I1 (io), G3 I/O70 I6 (io), G18 I/O121 P6 (io), G19 I/O125 P2 (io), H2 I/O64 I0 (io), H3 I/O66 I2 (io), H4 I/O67 I3 (io), H17 I/O124 P3 (io), H18 I/O126 P1 (io), H19 I/O127 P0 (io), M1 I/O62 H1 (io), M2 I/O63 H0 (io), N2 I/O59 H4 (io), N3 I/O61 H2 (io), N4 I/O60 H3 (io), N17 I/O3 A3 (io), N18 I/O2 A2 (io), N19 I/O0 A0 (io), P2 I/O58 H5 (io), P3 I/O57 H6 (io), P18 I/O6 A6 (io), P19 I/O1 A1 (io), R2 I/O56 H7 (io), R3 I/O54 G1 (io), R4 I/O51 G4 (io), R18 I/O9 B1 (io), R19 I/O5 A5 (io), T2 I/O55 G0 (io), T3 I/O50 G5 (io), T18 I/O12 B4 (io), T19 I/O8 B0 (io), T20 I/O4 A4 (io), U2 I/O53 G2 (io), U3 I/O48 G7 (io), U9 I/O35 E3 (io), U12 I/O29 D2 (io), U13 I/O24 D7 (io), U15 I/O18 C5 (io), U18 I/O15 B7 (io), U19 I/O11 B3 (io), U20 I/O7 A7 (io), V2 I/O52 G3 (io), V4 I/O47 F7 (io), V5 I/O46 F6 (io), V6 I/O43 F3 (io), V7 I/O41 F1 (io), V8 I/O37 E5 (io), V9 I/O33 E1 (io), V12 I/O31 D0 (io), V13 I/O27 D4 (io), V14 I/O23 C0 (io), V15 I/O21 C2 (io), V16 I/O17 C6 (io), V17 I/O16 C7 (io), V19 I/O13 B5 (io), V20 I/O10 B2 (io), W2 I/O49 G6 (io), W4 I/O45 F5 (io), W5 I/O42 F2 (io), W6 I/O39 E7 (io), W7 I/O38 E6 (io), W8 I/O34 E2 (io), W13 I/O28 D3 (io), W14 I/O25 D6 (io), W15 I/O22 C1 (io), W16 I/O19 C4 (io), W19 I/O14 B6 (io), Y4 I/O44 F4 (io), Y5 I/O40 F0 (io), Y7 I/O36 E4 (io), Y8 I/O32 E0 (io), Y13 I/O30 D1 (io), Y14 I/O26 D5 (io), Y16 I/O20 C3 (io)
part B pins: A1 GND (power), A2 GND (power), A3 GND (power), A6 GND (power), A9 GND (power), A10 GND (power), A11 GND (power), A12 GND (power), A15 GND (power), A18 GND (power), A20 GND (power), B1 GND (power), B11 I11 (in), B20 GND (power), C3 VCC (power), C4 ~{ENABLE} (in), C10 I10 (in), C17 ~{TRST} (in), C18 VCC (power), D4 VCC (power), D5 VCC (power), D7 VCC (power), D10 I9 (in), D14 VCC (power), D16 VCC (power), D17 VCC (power), E4 TDO (out), E17 TDI (in), F1 GND (power), F20 GND (power), G1 I8 (in), G4 VCC (power), G17 VCC (power), G20 I12 (in), H1 GND (power), H20 GND (power), J4 I7 (in), J17 I13 (in), K2 CLK2 (in), K19 CLK3 (in), K20 GND (power), L1 GND (power), L2 CLK1 (in), L19 CLK0 (in), M4 I6 (in), M17 I0 (in), N1 GND (power), N20 GND (power), P1 I5 (io), P4 VCC (power), P17 VCC (power), P20 I1 (in), R1 GND (power), R20 GND (power), T4 TMS (in), T17 TCK (in), U4 VCC (power), U5 VCC (power), U7 VCC (power), U11 I2 (in), U14 VCC (power), U16 VCC (power), U17 VCC (power), V3 VCC (power), V11 I3 (in), V18 VCC (power), W1 GND (power), W10 I4 (in), W20 GND (power), Y1 GND (power), Y3 GND (power), Y6 GND (power), Y9 GND (power), Y10 GND (power), Y11 GND (power), Y12 GND (power), Y15 GND (power), Y18 GND (power), Y19 GND (power), Y20 GND (power)
part C pins: A4 NC, A19 NC, B2 NC, B9 NC, B10 NC, B12 NC, B18 NC, C11 NC, C19 NC, D8 NC, D11 NC, D13 NC, J1 NC, J2 NC, J3 NC, J18 NC, J19 NC, J20 NC, K1 NC, K3 NC, K4 NC, K17 NC, K18 NC, L3 NC, L4 NC, L17 NC, L18 NC, L20 NC, M3 NC, M18 NC, M19 NC, M20 NC, R17 NC, T1 NC, U1 NC, U6 NC, U8 NC, U10 NC, V1 NC, V10 NC, W3 NC, W9 NC, W11 NC, W12 NC, W17 NC, W18 NC, Y2 NC, Y17 NC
